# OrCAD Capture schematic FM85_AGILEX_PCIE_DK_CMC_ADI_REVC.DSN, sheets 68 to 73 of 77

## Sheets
68 1p2V_PRE: size B
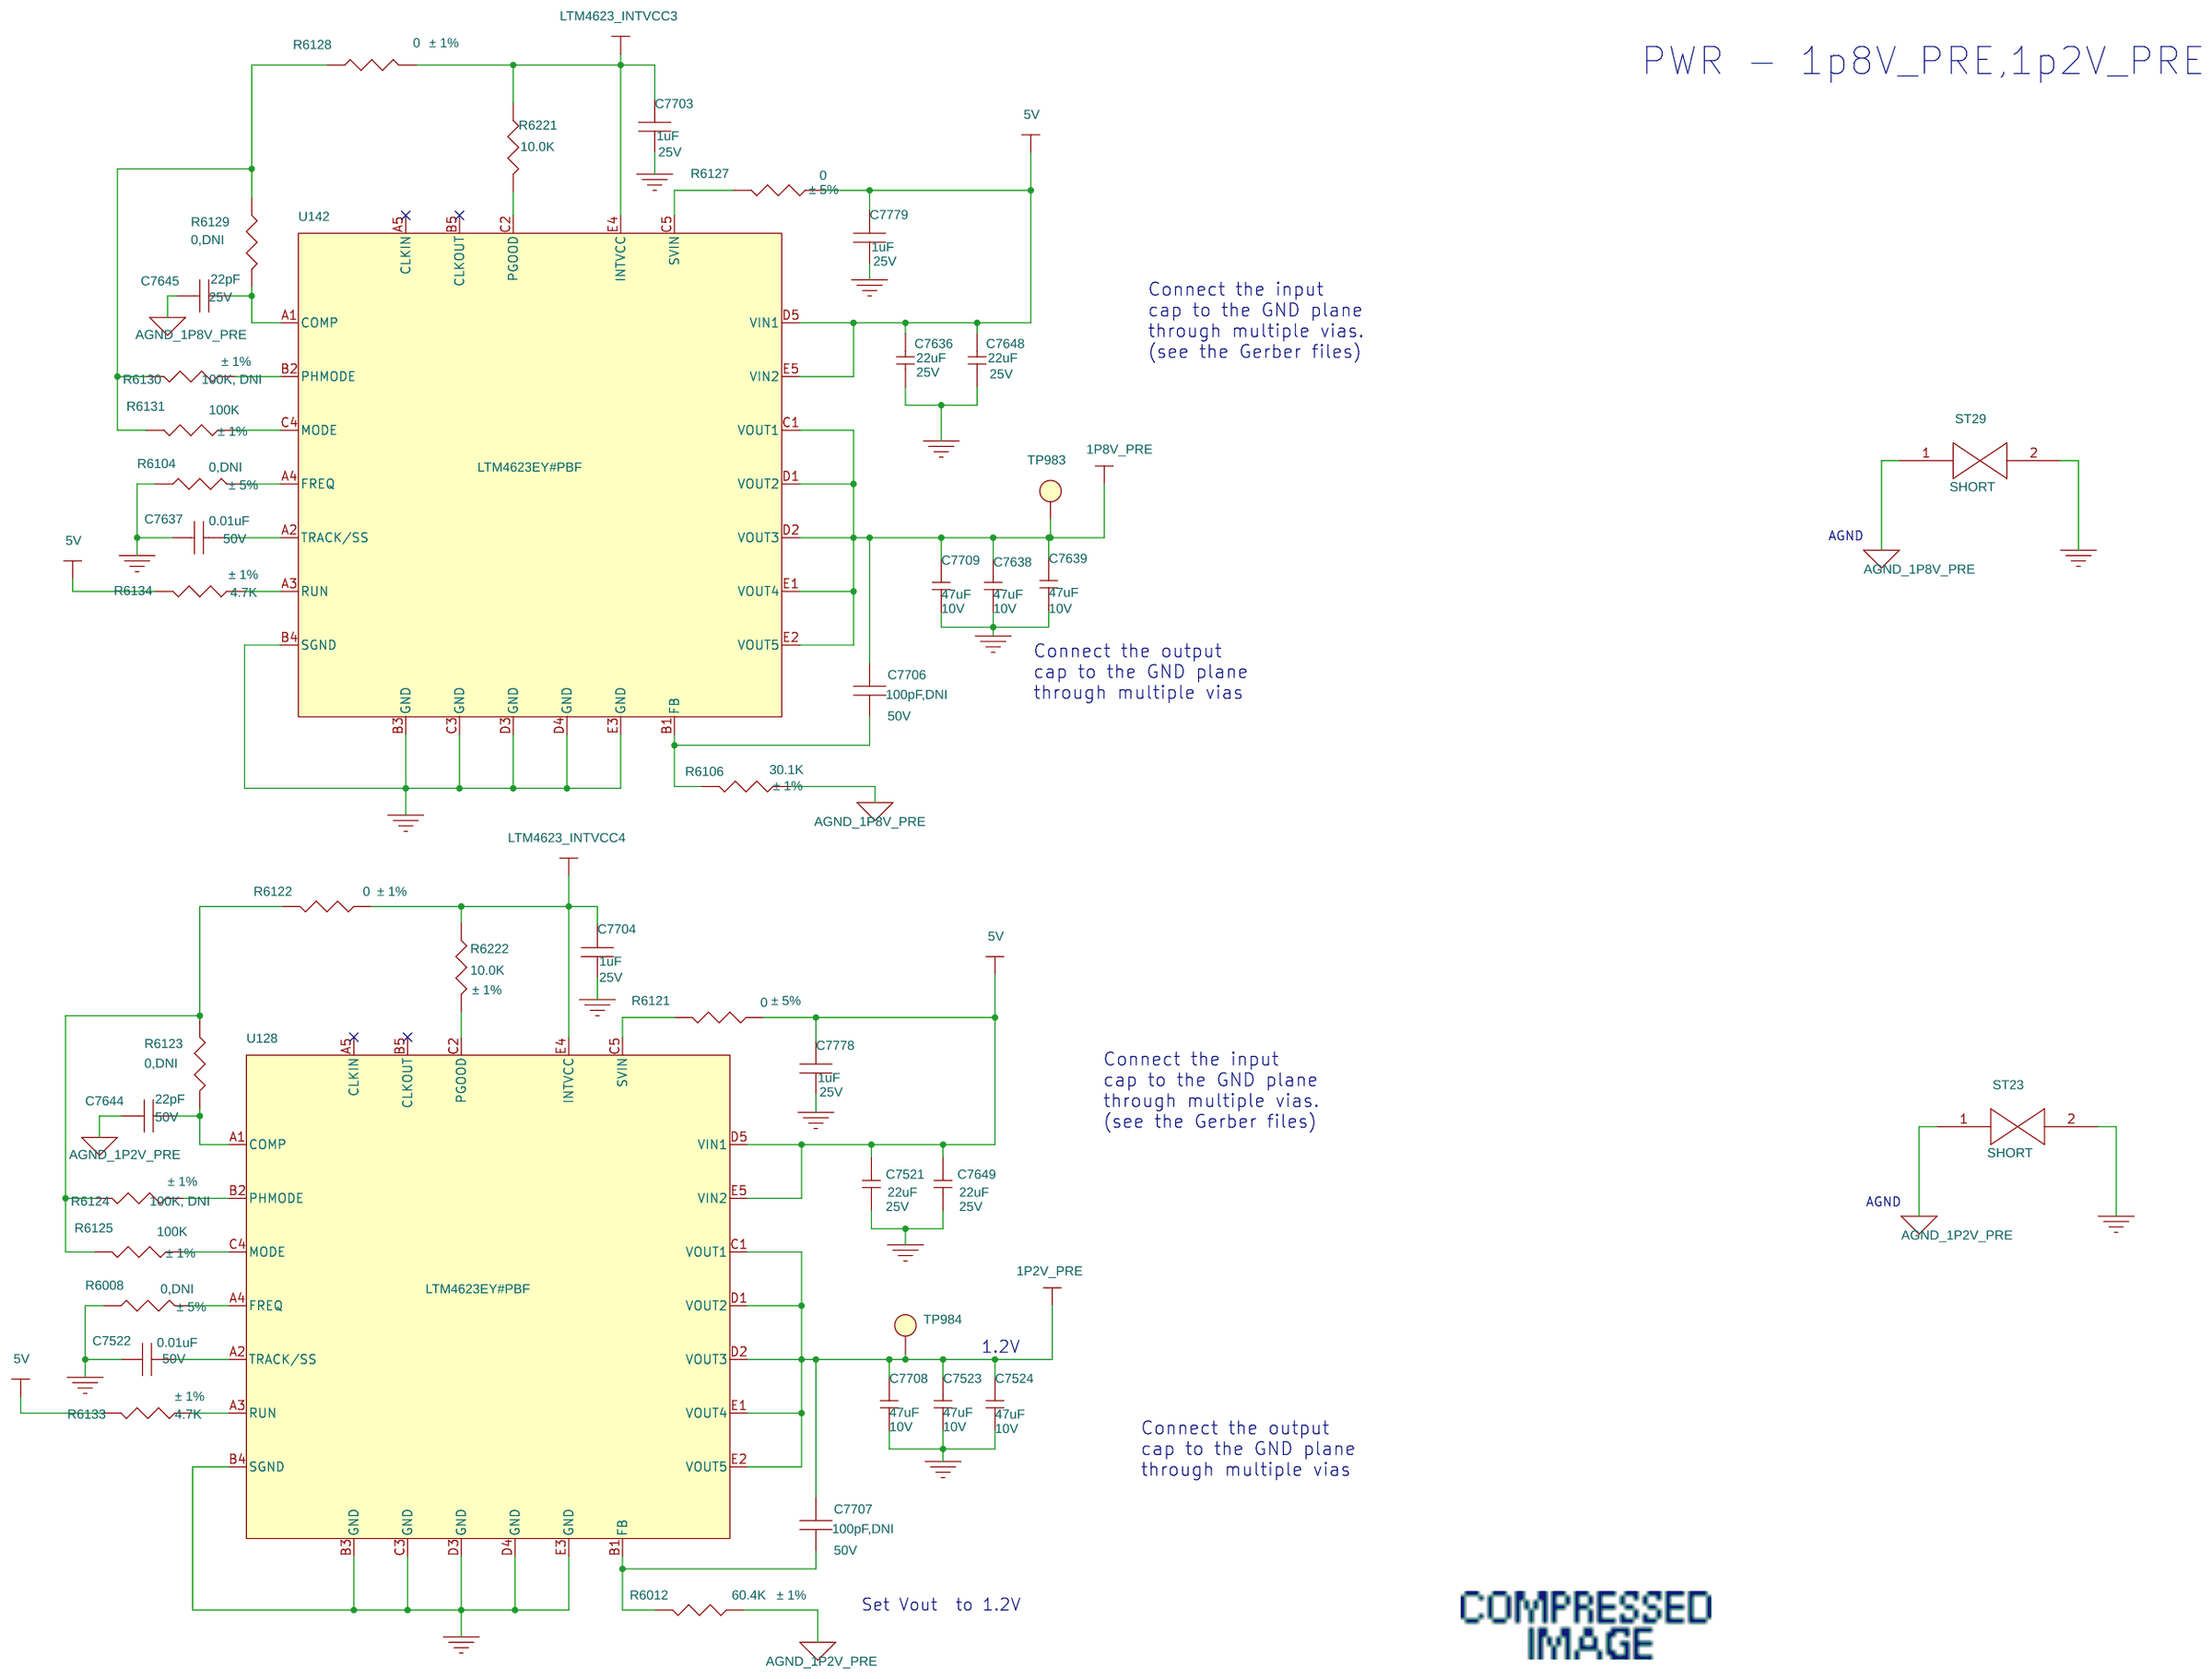
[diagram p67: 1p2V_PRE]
69 PWR-VCCFUSEWR_SDM: size B
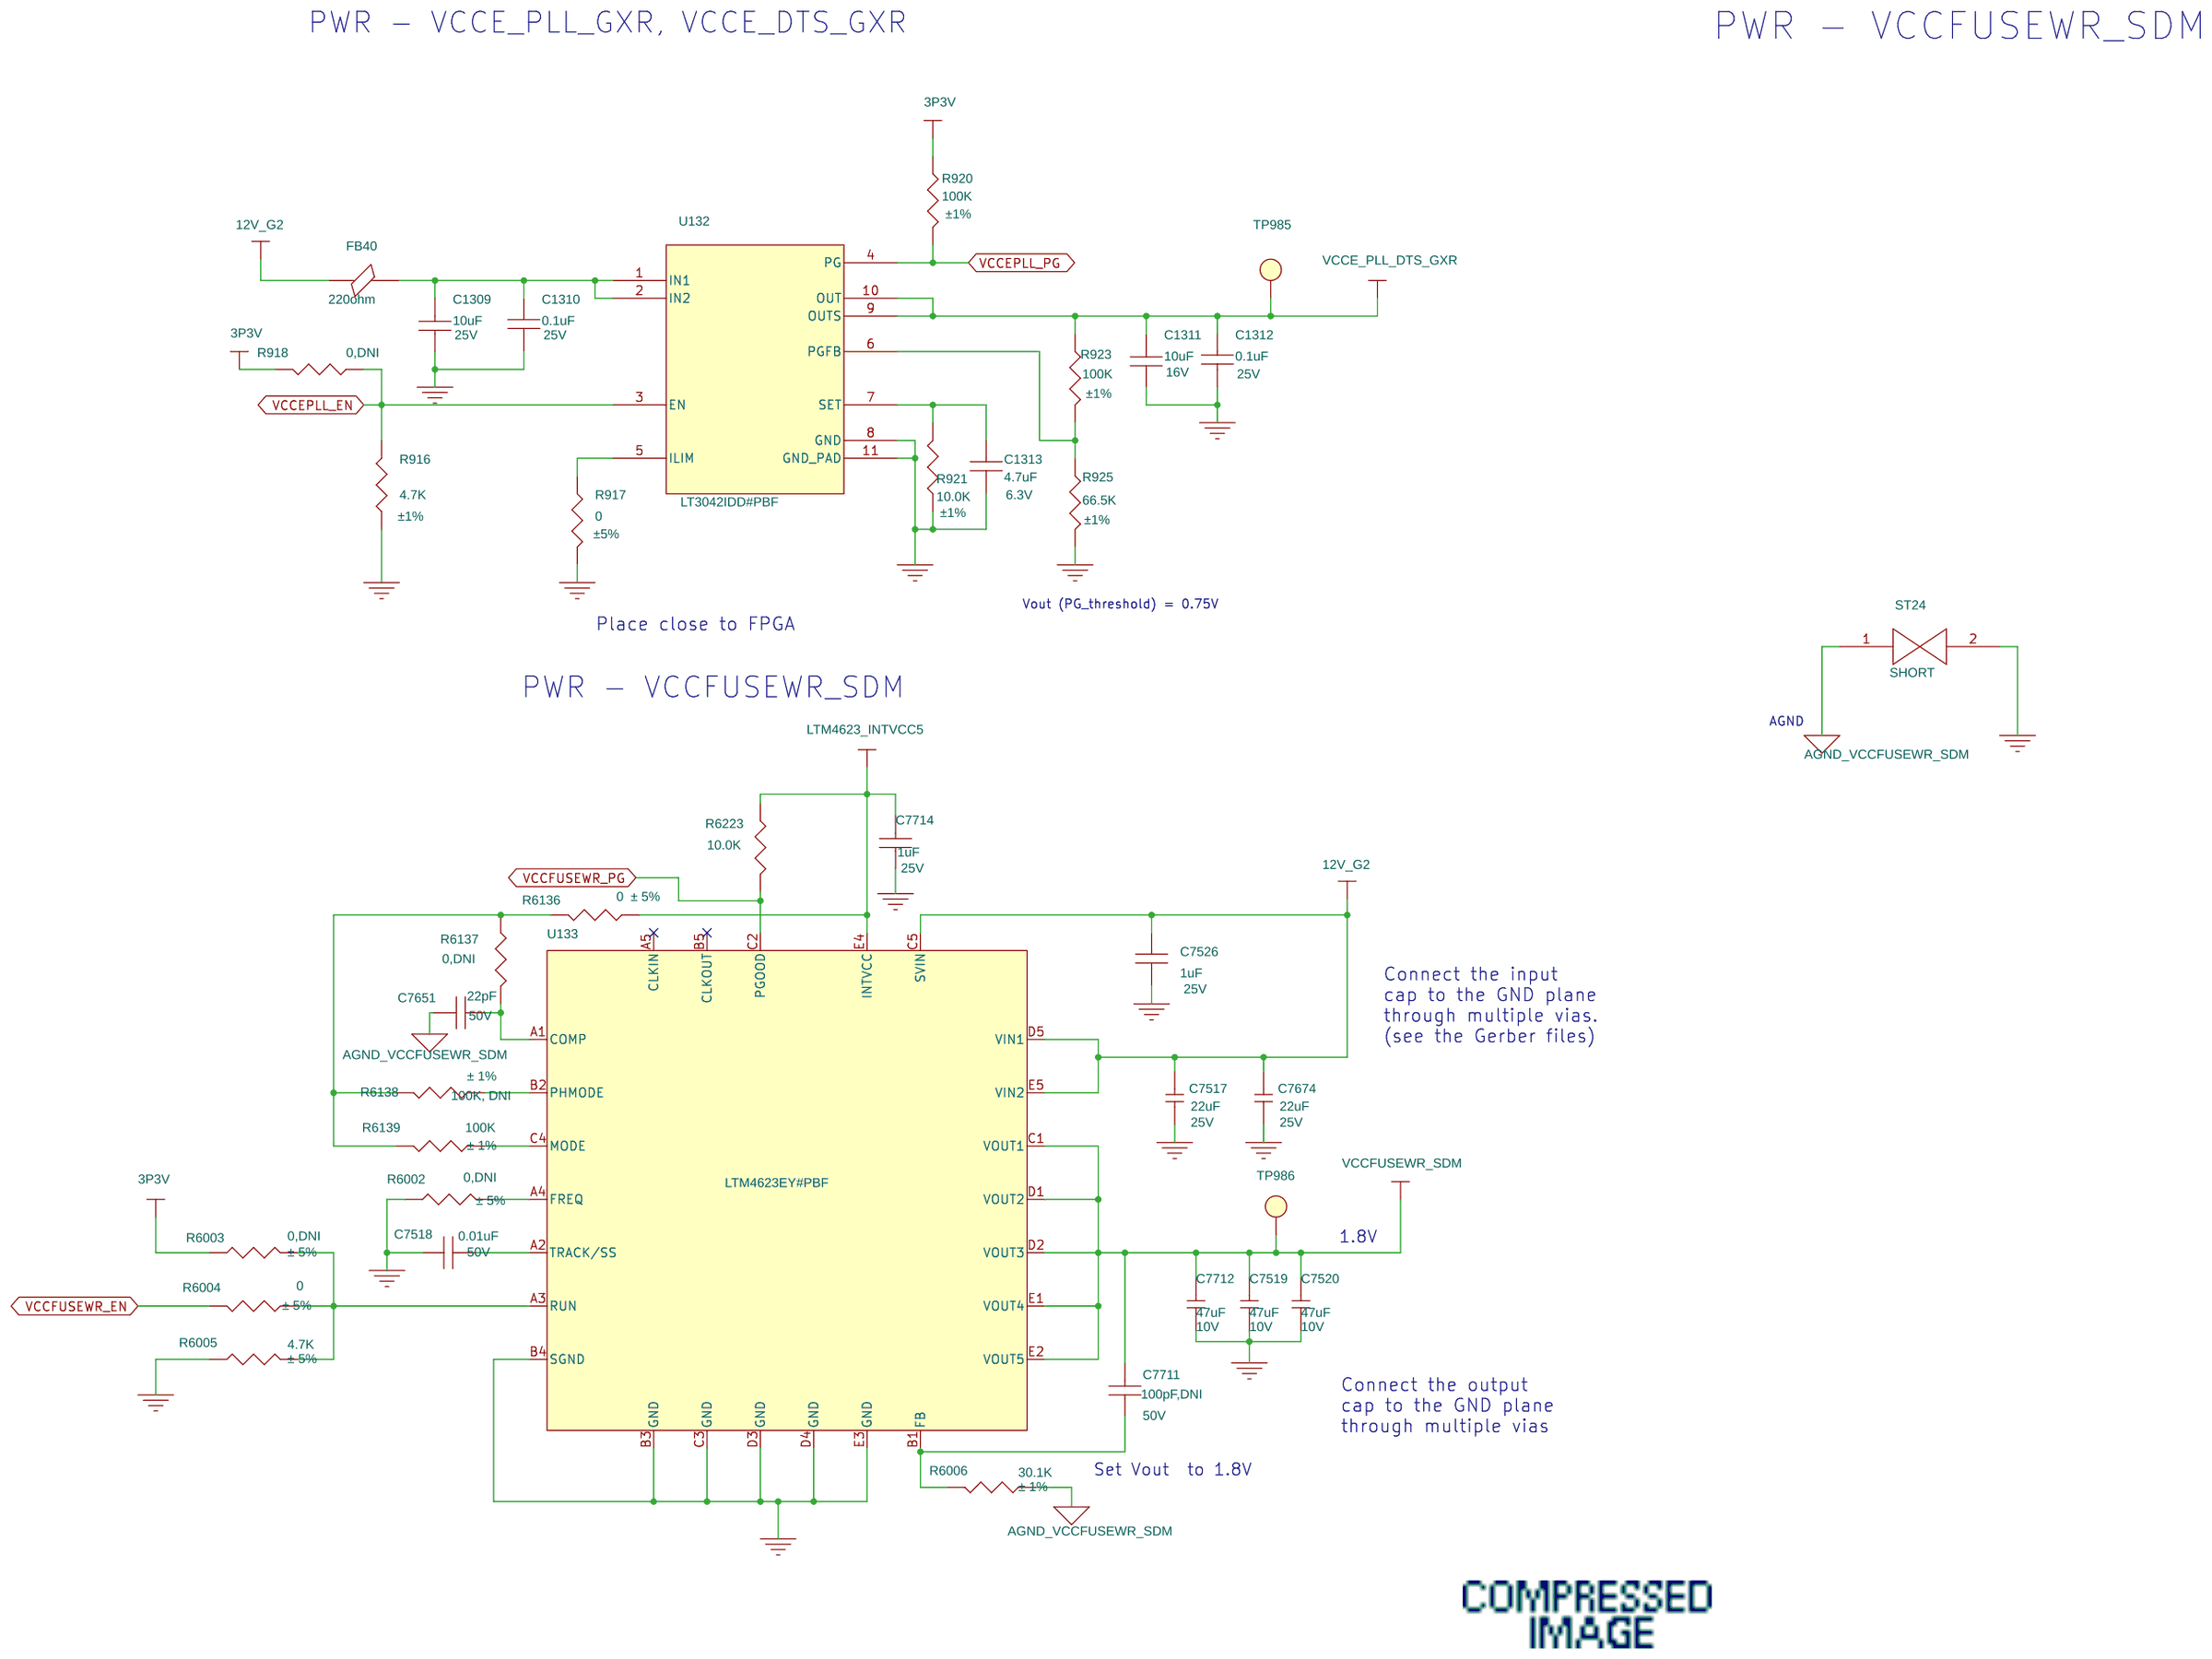
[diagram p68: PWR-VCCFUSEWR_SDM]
70 PWR - 1p2V_DDR4_CH01_OK: size B
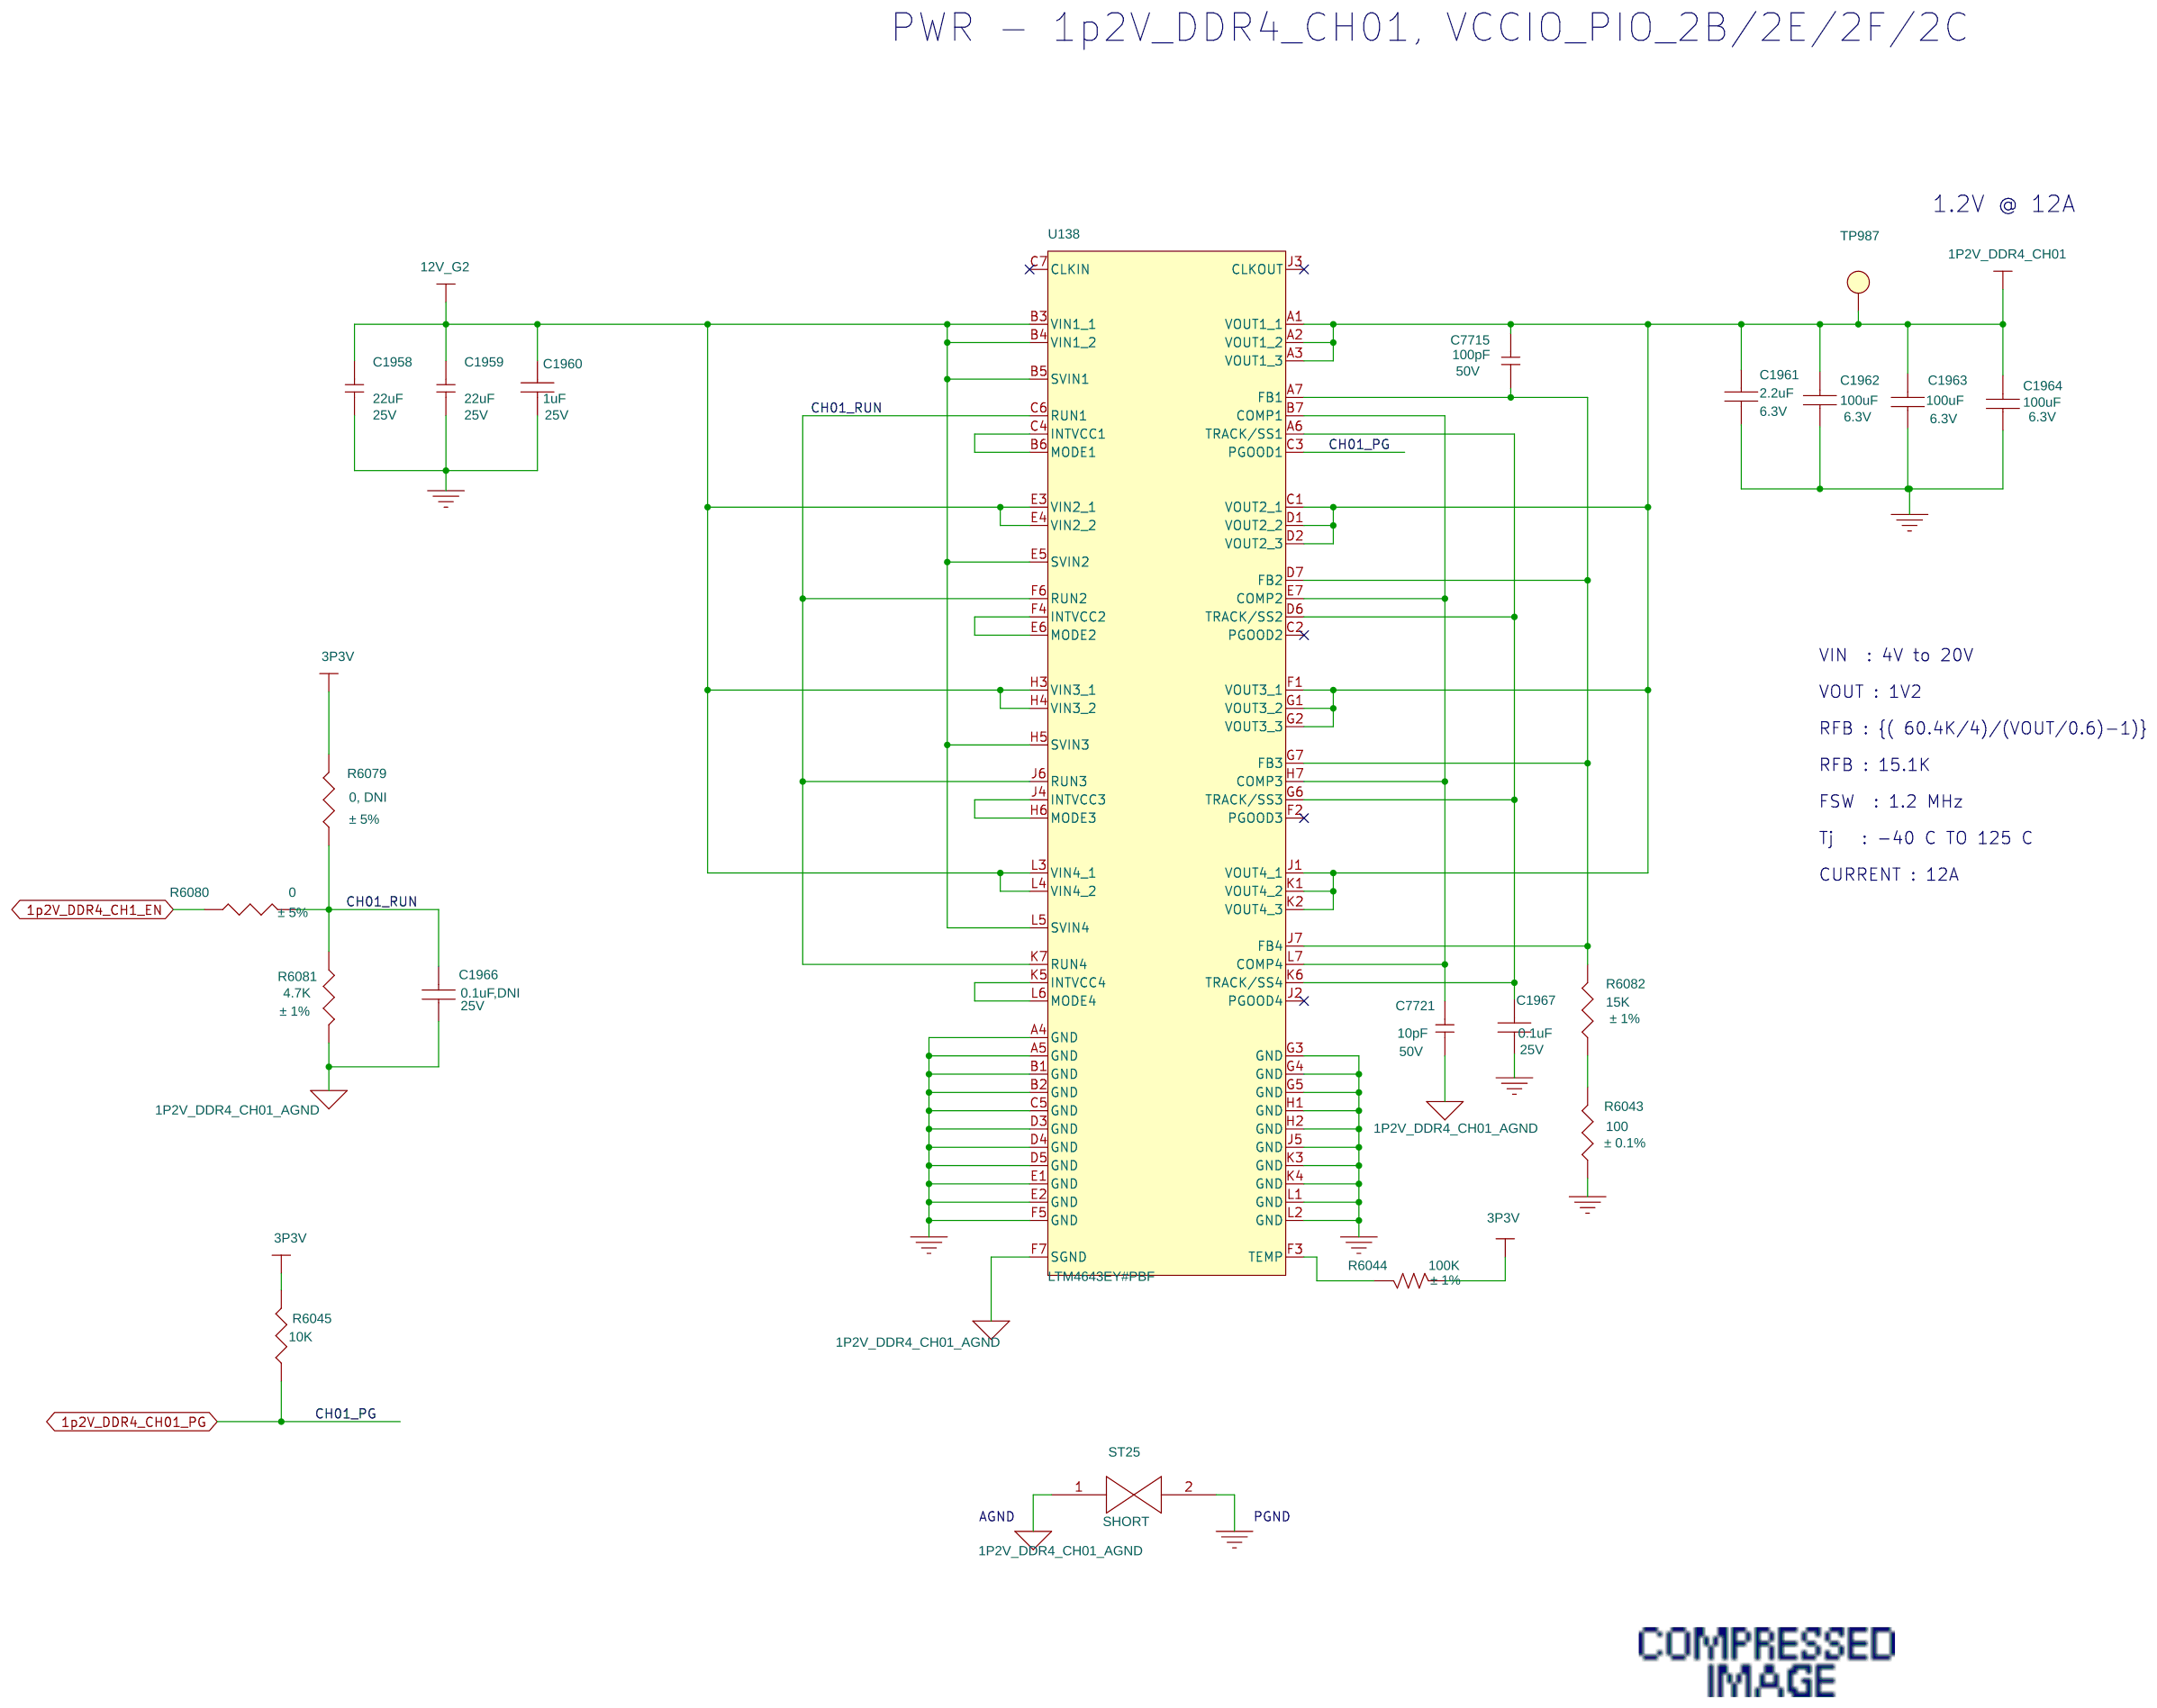
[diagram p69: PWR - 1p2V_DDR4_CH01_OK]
71 PWR - 1p2V_DDR4_CH2_OK: size B
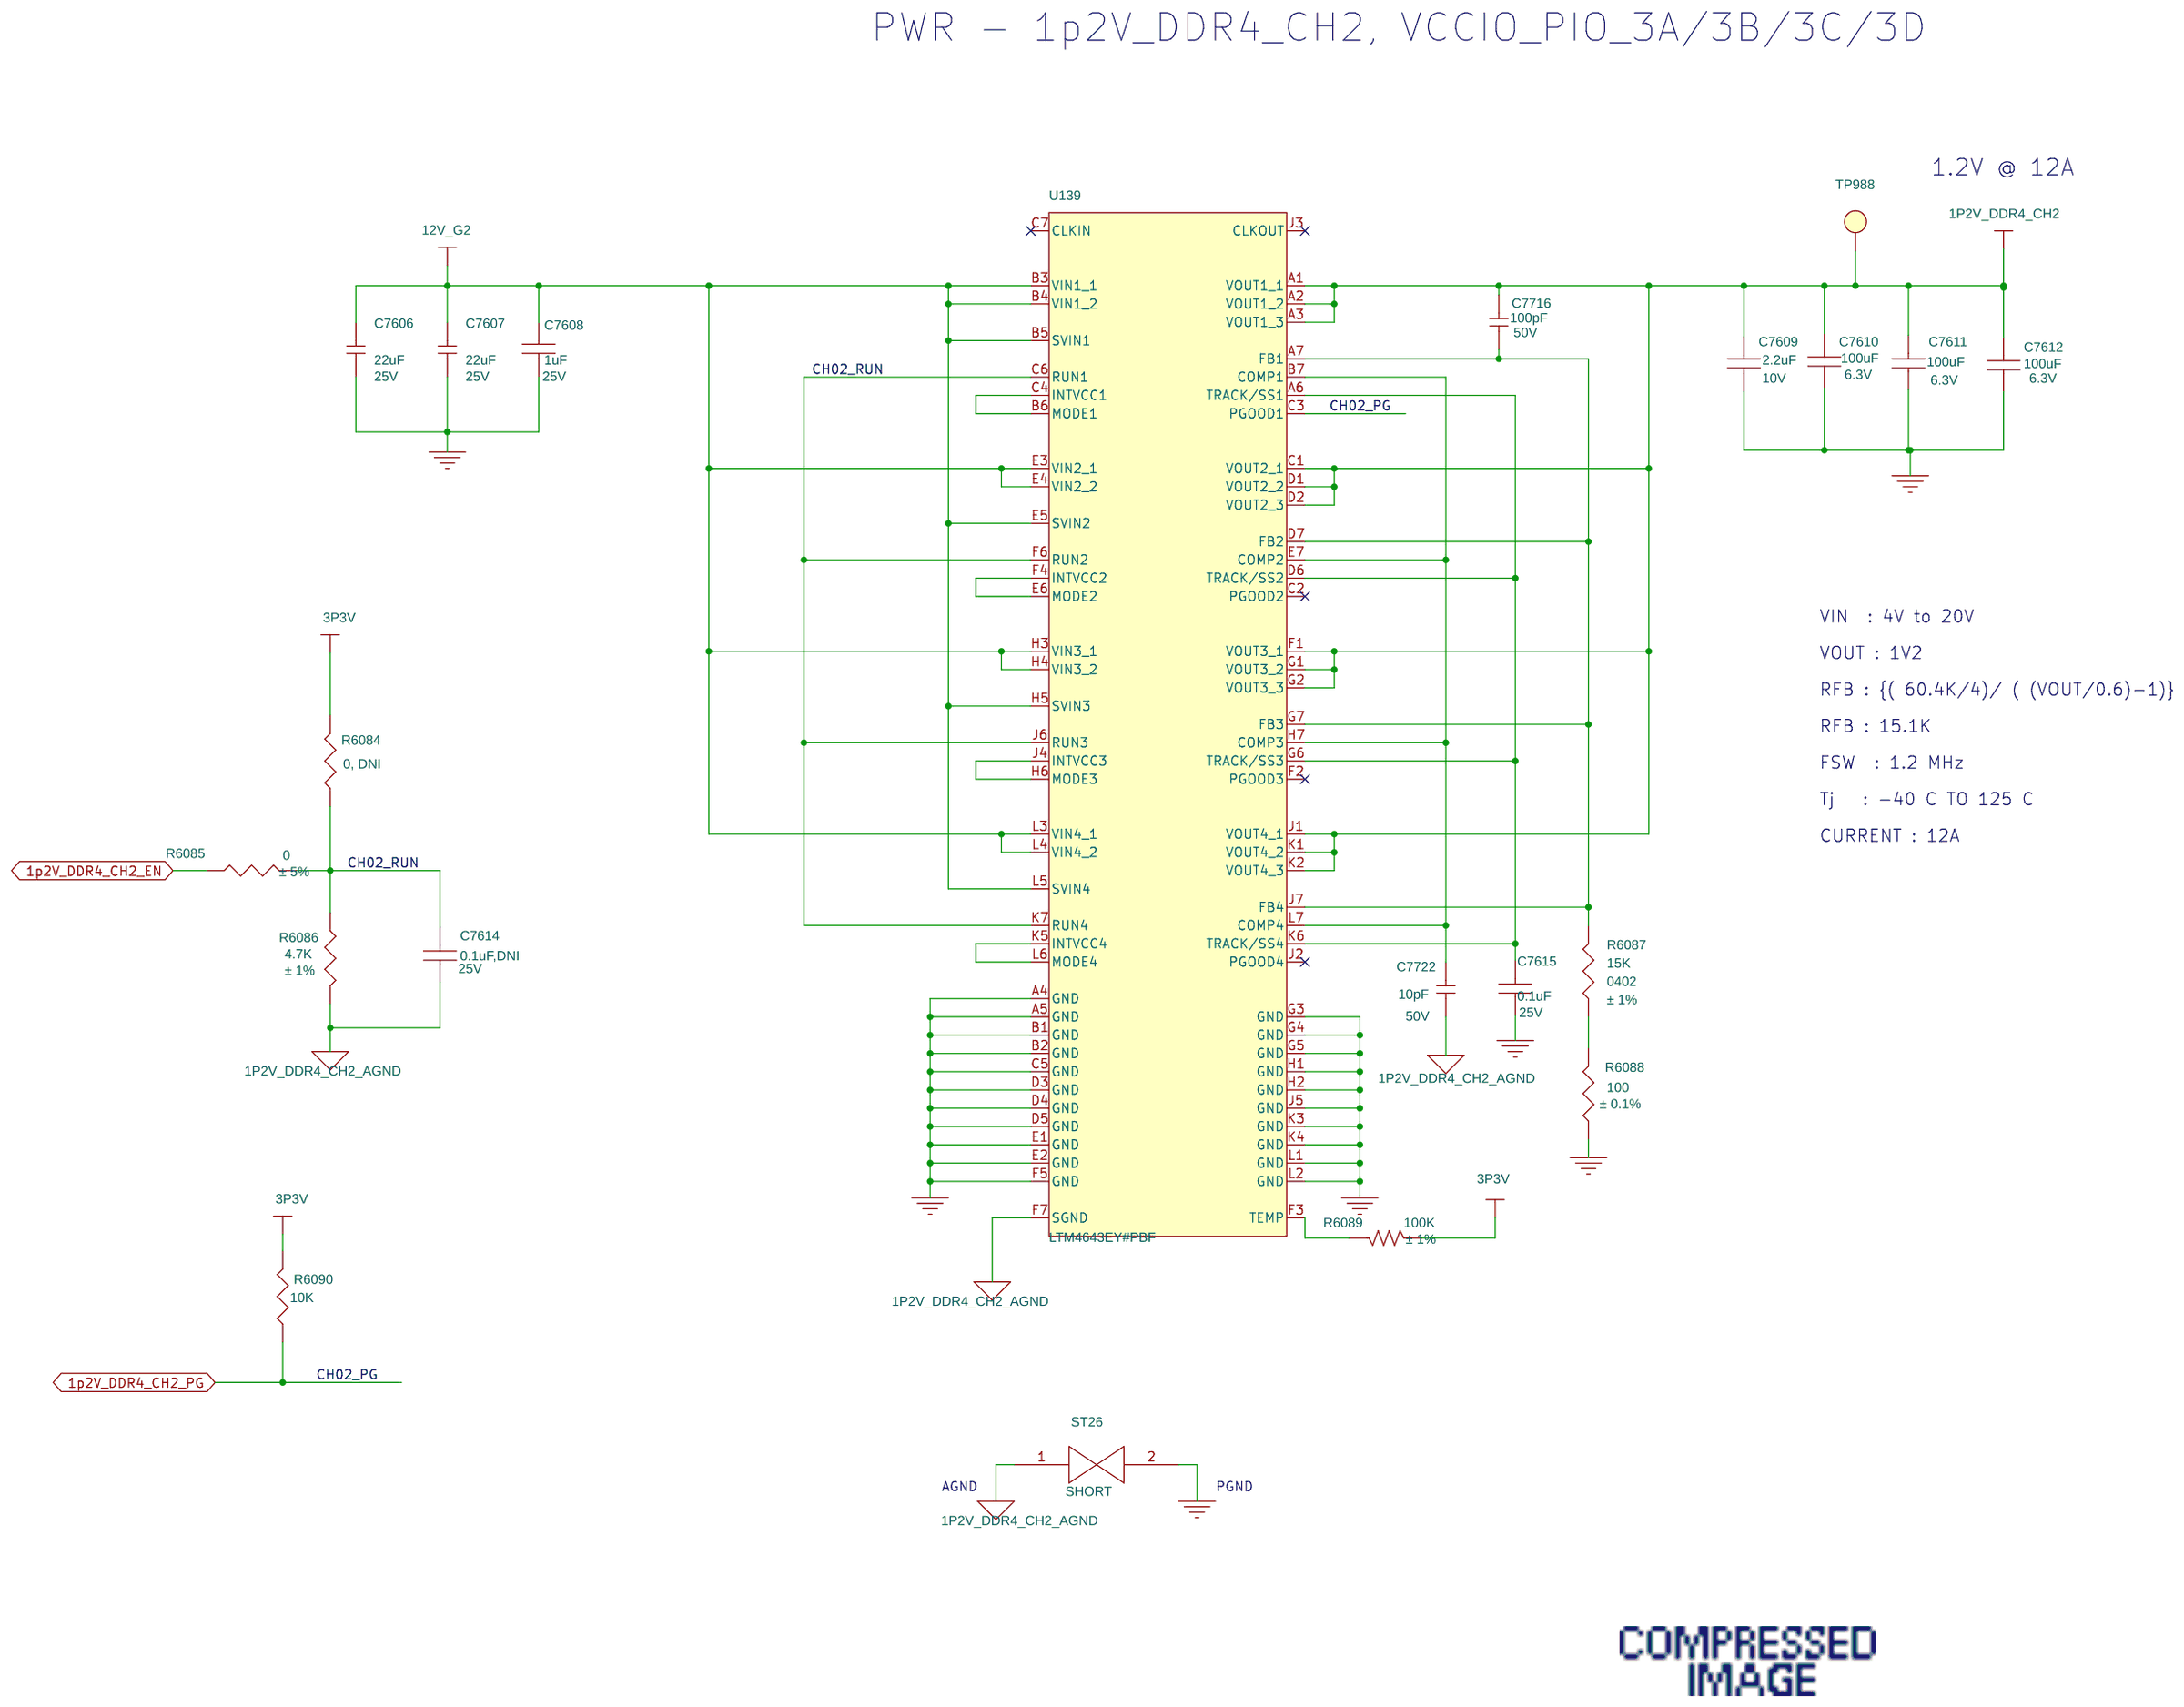
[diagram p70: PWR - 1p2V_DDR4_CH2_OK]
72 PWR - 0p6V_VTT/VREF_OK: size B
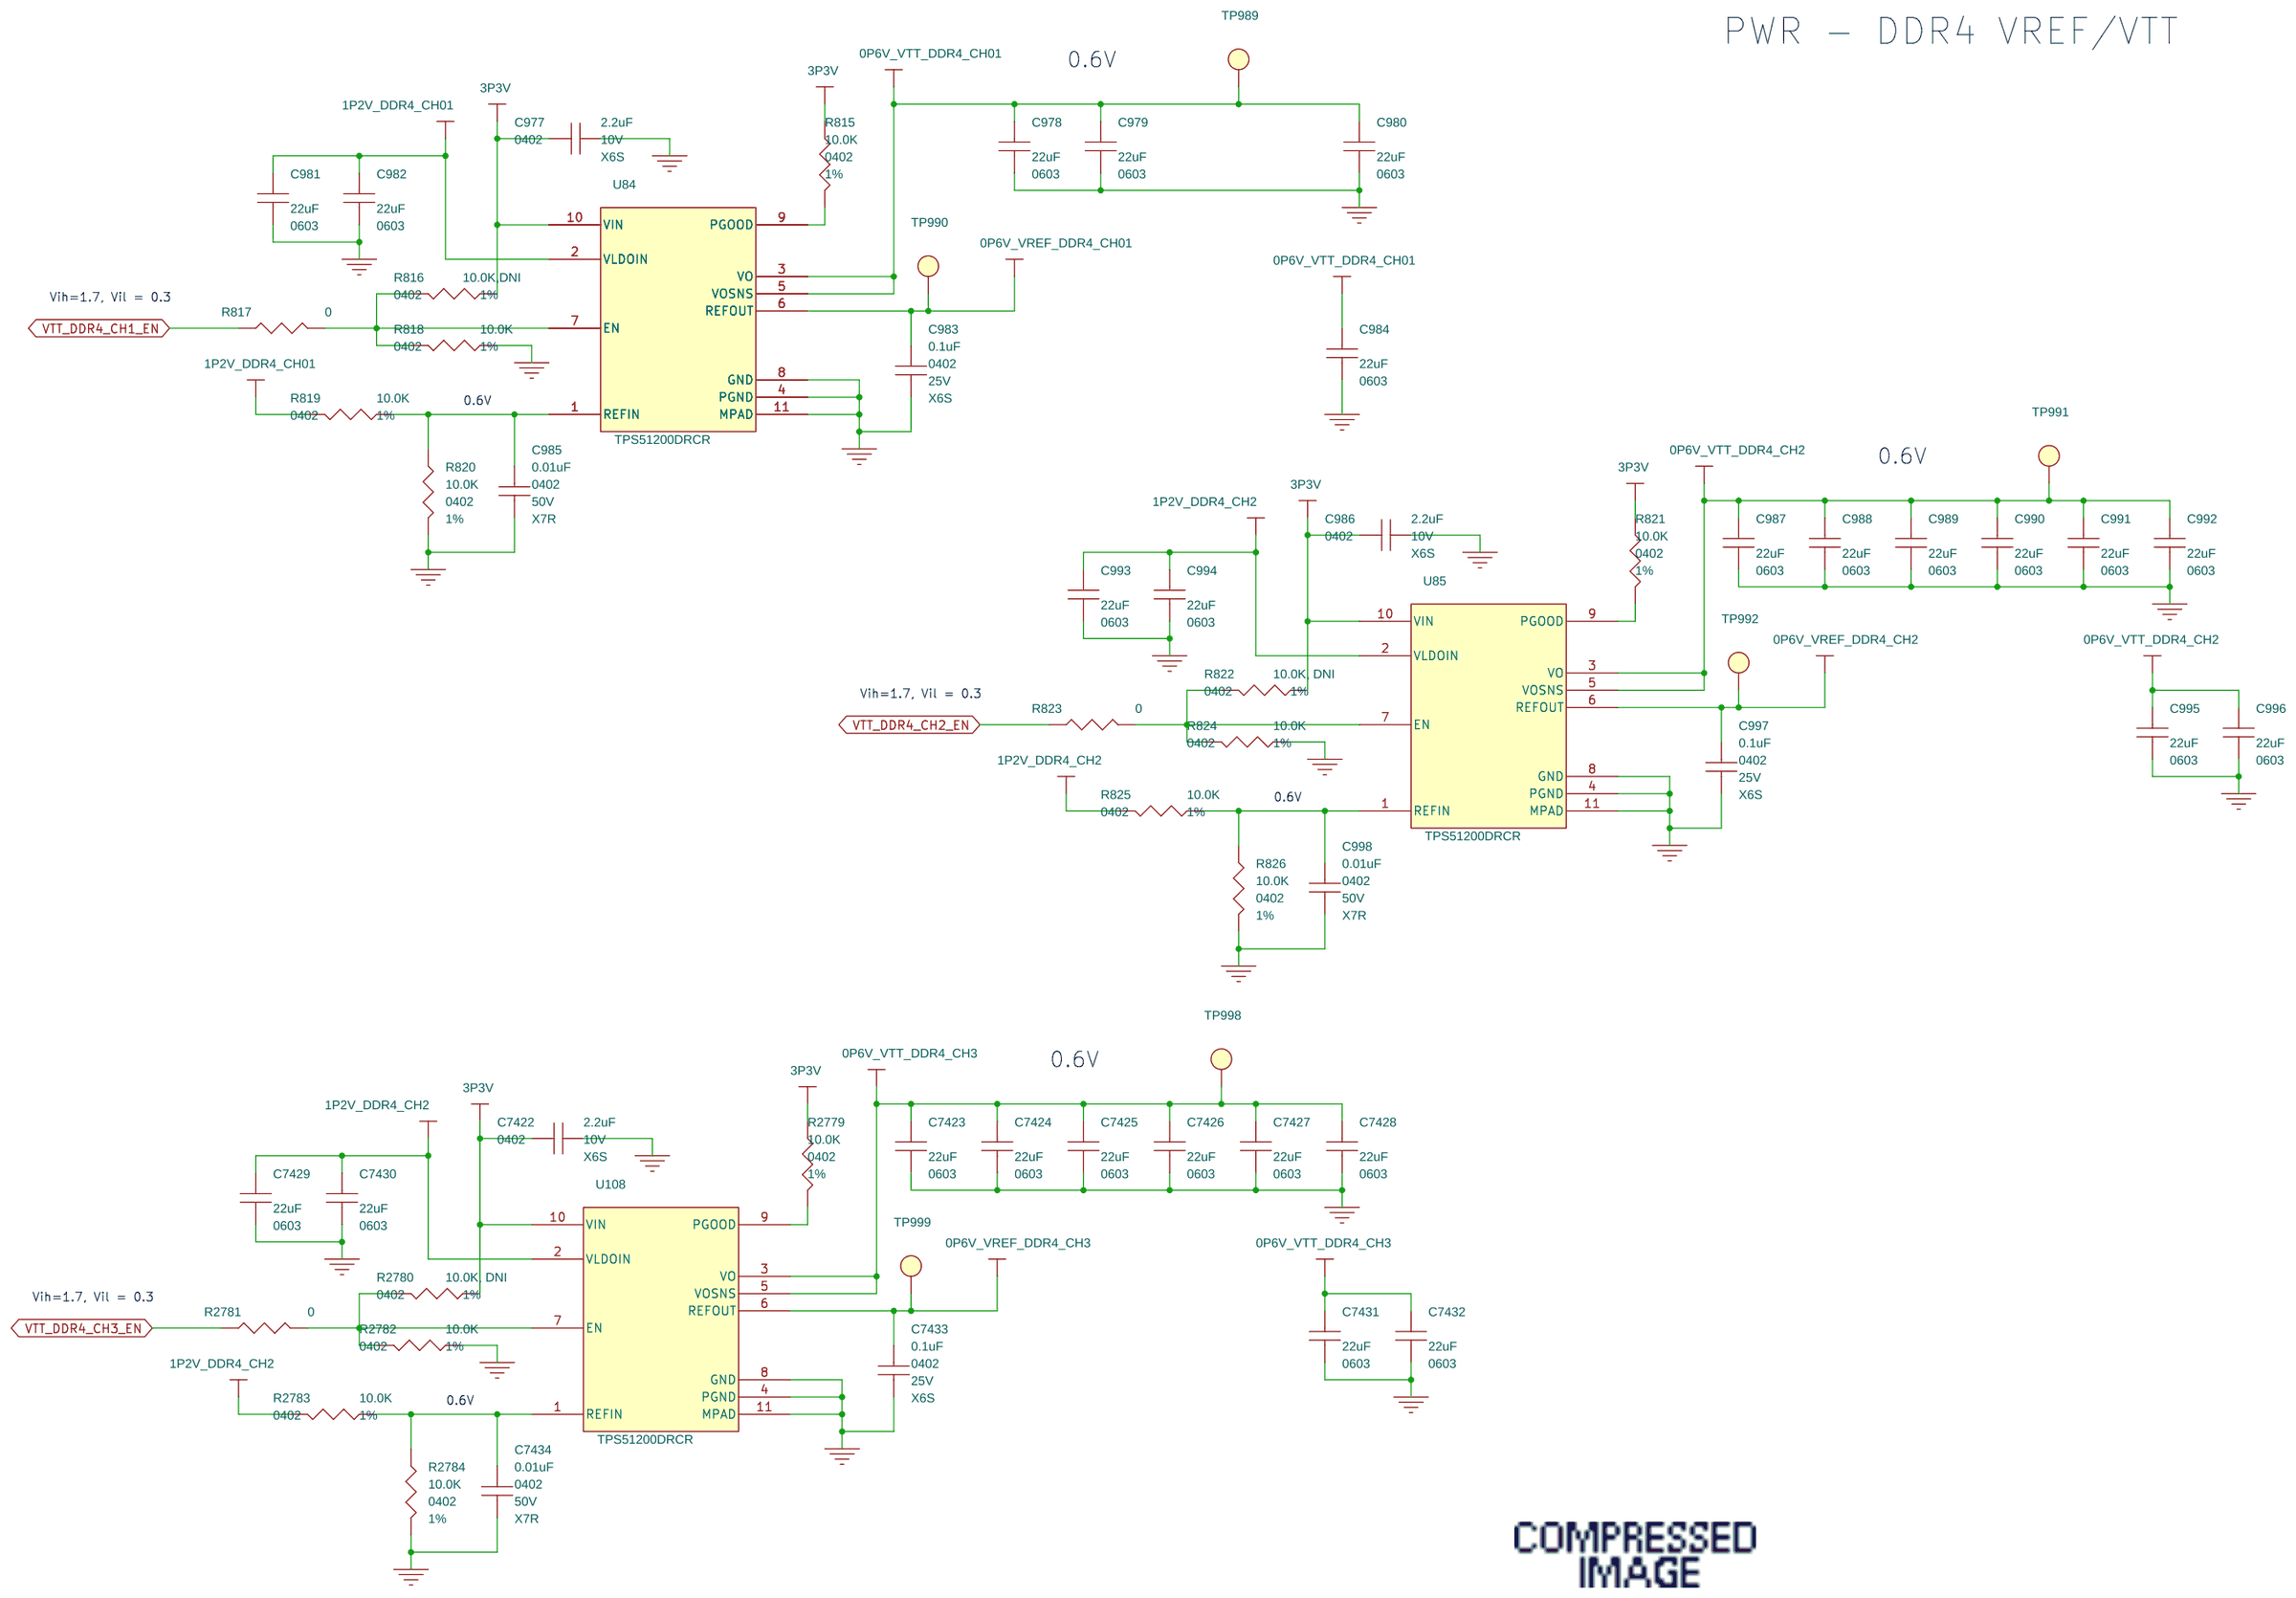
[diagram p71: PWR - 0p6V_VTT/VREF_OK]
73 PWR - 2p5V_OK: size B
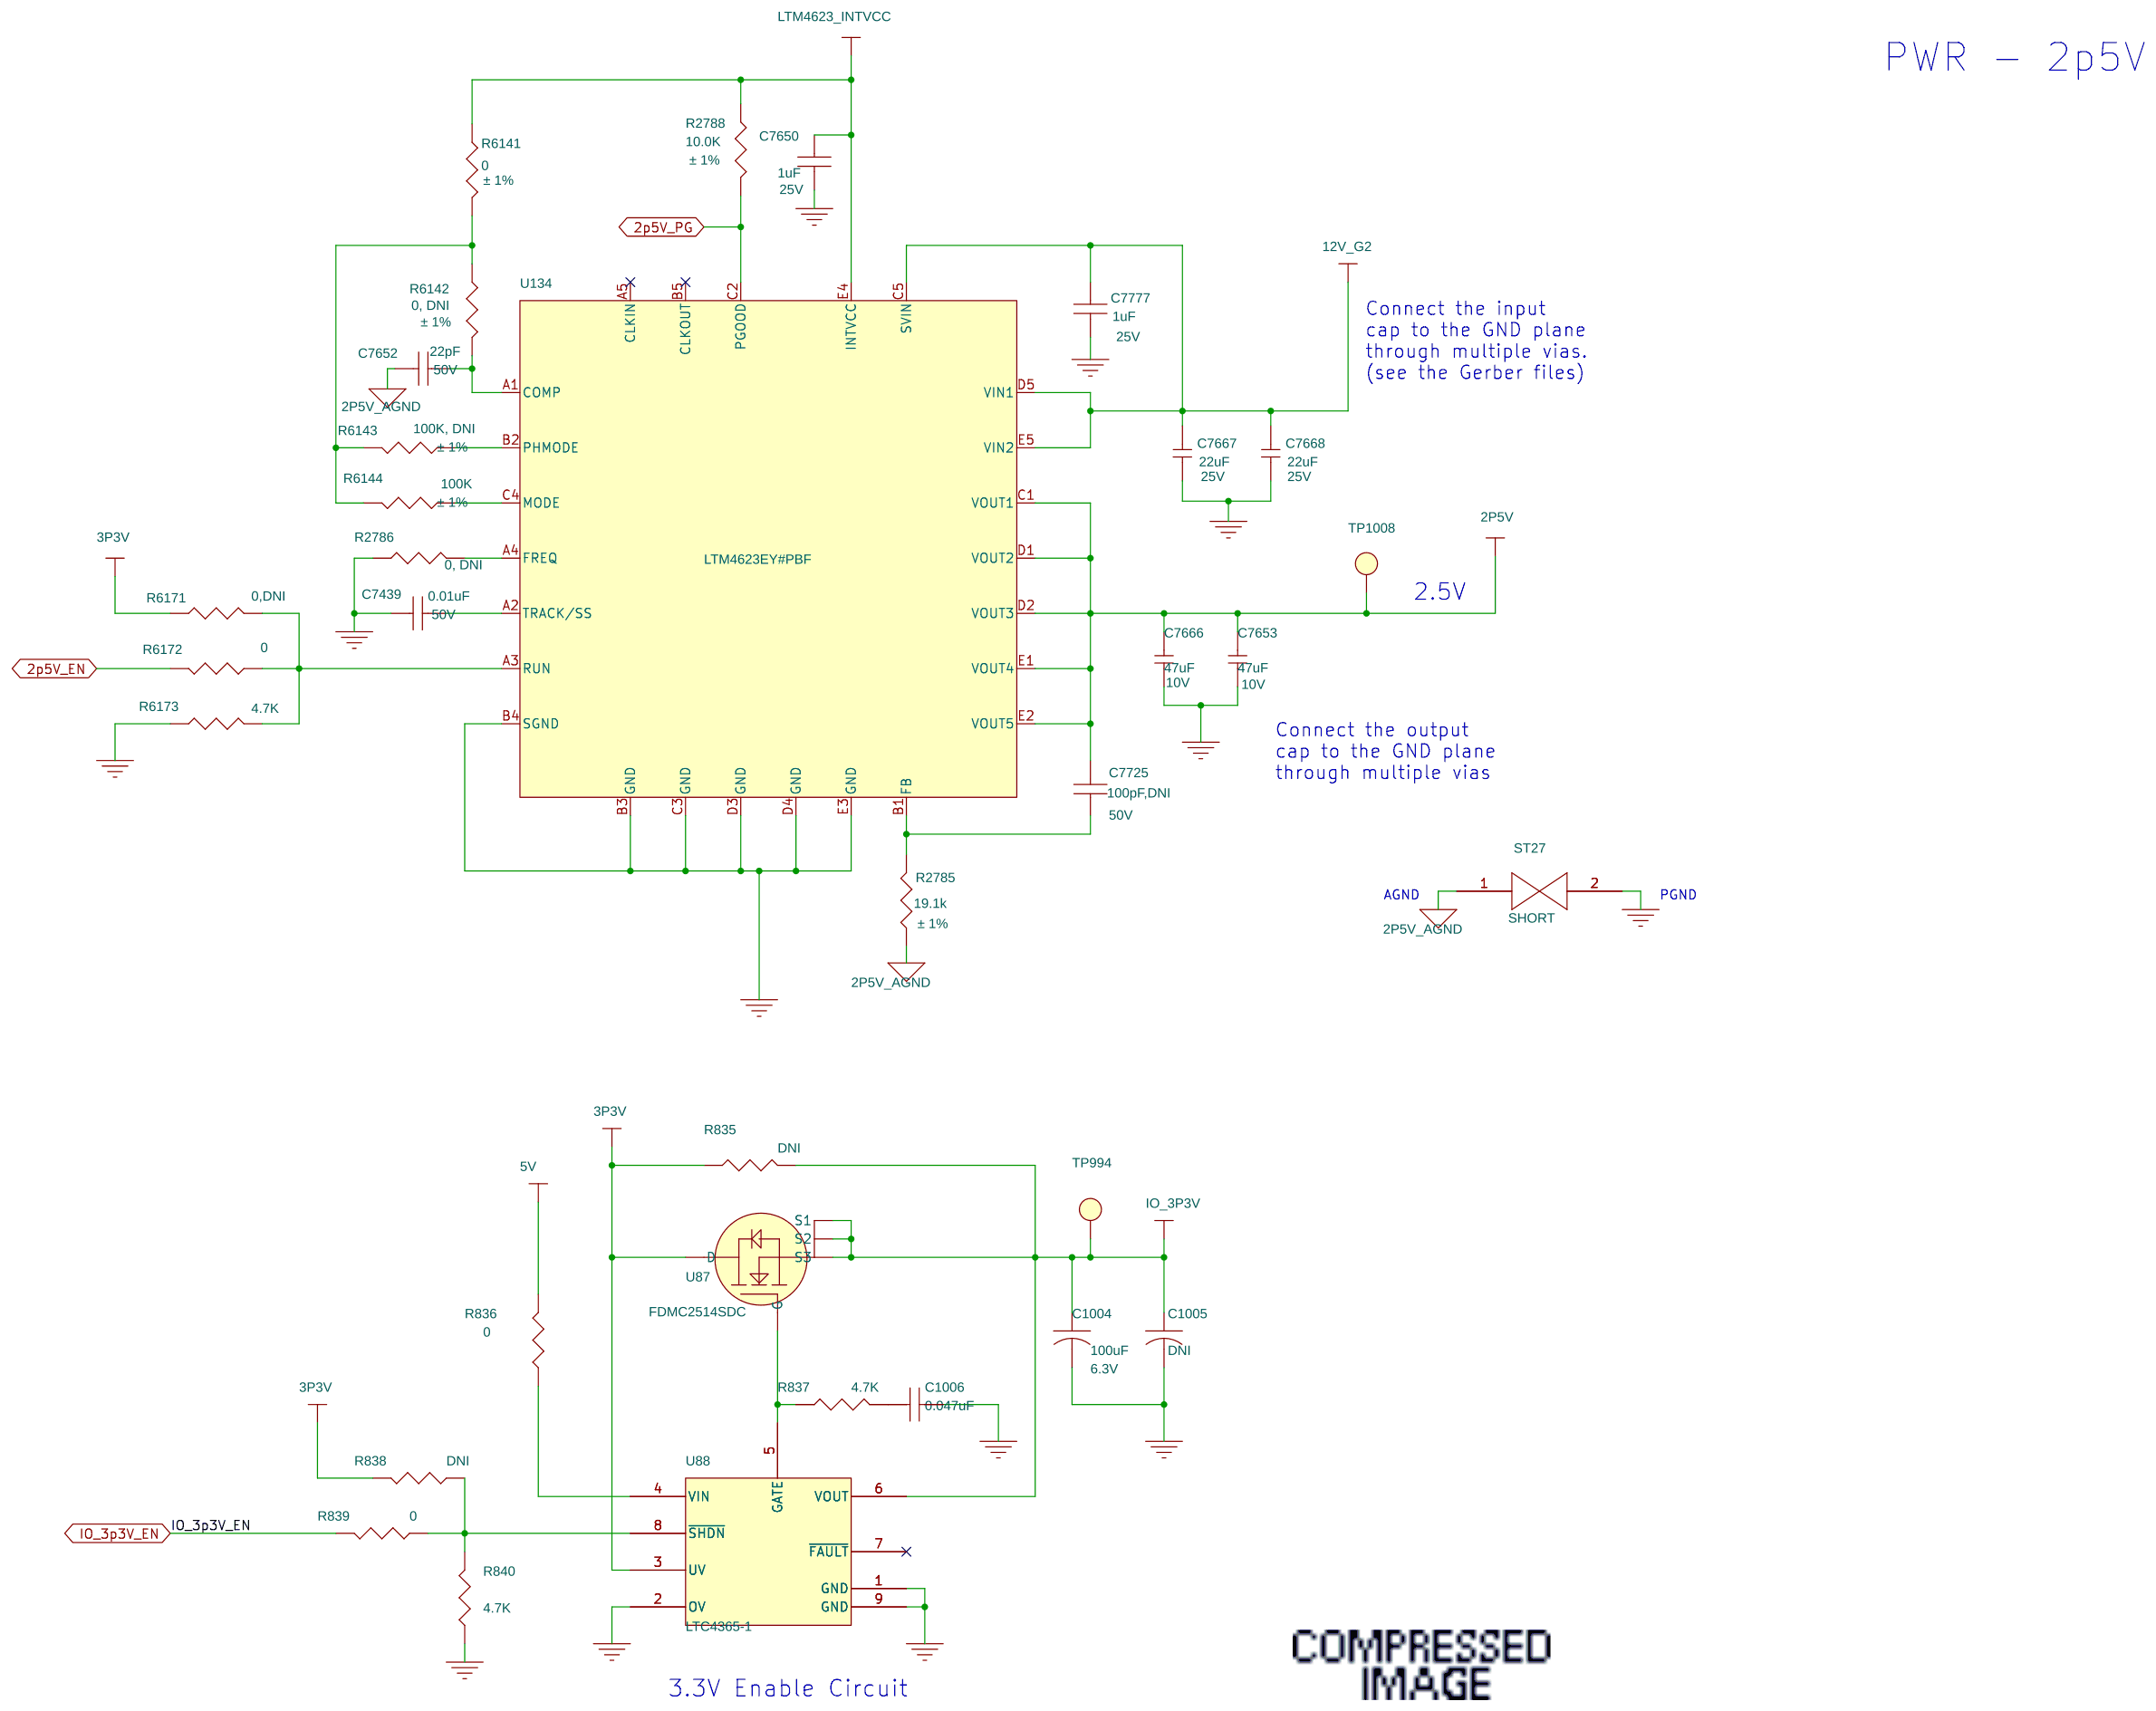
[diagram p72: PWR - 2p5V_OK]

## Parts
sheet 1p2V_PRE
C7521  22uF  [1206]
C7522  0.01uF  [0402]
C7523  47uF  [C1206]
C7524  47uF  [C1206]
C7636  22uF  [1206]
C7637  0.01uF  [0402]
C7638  47uF  [C1206]
C7639  47uF  [C1206]
C7644  22pF  [0603]
C7645  22pF  [0603]
C7648  22uF  [1206]
C7649  22uF  [1206]
C7703  1uF  [0402]
C7704  1uF  [0402]
C7706  100pF,DNI  [0402]
C7707  100pF,DNI  [0402]
C7708  47uF  [C1206]
C7709  47uF  [C1206]
C7778  1uF  [0402]
C7779  1uF  [0402]
R6008  0,DNI  [0402]
R6012  60.4K  [0402]
R6104  0,DNI  [0402]
R6106  30.1K  [0402]
R6121  0  [0402]
R6122  0  [0402]
R6123  0,DNI  [0402]
R6124  100K, DNI  [0402]
R6125  100K  [0402]
R6127  0  [0402]
R6128  0  [0402]
R6129  0,DNI  [0402]
R6130  100K, DNI  [0402]
R6131  100K  [0402]
R6133  4.7K  [0402]
R6134  4.7K  [0402]
R6221  10.0K  [0402]
R6222  10.0K  [0402]
ST23  SHORT  [SHORT]
ST29  SHORT  [SHORT]
TP983  TESTPOINT  [30MIL_TP]
TP984  TESTPOINT  [30MIL_TP]
U128  LTM4623EY#PBF  [BGA25C127P5X5_625X625X262]
U142  LTM4623EY#PBF  [BGA25C127P5X5_625X625X262]
sheet PWR - 0p6V_VTT/VREF_OK
C977  2.2uF  [0402]
C978  22uF  [0603]
C979  22uF  [0603]
C980  22uF  [0603]
C981  22uF  [0603]
C982  22uF  [0603]
C983  0.1uF  [0402]
C984  22uF  [0603]
C985  0.01uF  [0402]
C986  2.2uF  [0402]
C987  22uF  [0603]
C988  22uF  [0603]
C989  22uF  [0603]
C990  22uF  [0603]
C991  22uF  [0603]
C992  22uF  [0603]
C993  22uF  [0603]
C994  22uF  [0603]
C995  22uF  [0603]
C996  22uF  [0603]
C997  0.1uF  [0402]
C998  0.01uF  [0402]
C7422  2.2uF  [0402]
C7423  22uF  [0603]
C7424  22uF  [0603]
C7425  22uF  [0603]
C7426  22uF  [0603]
C7427  22uF  [0603]
C7428  22uF  [0603]
C7429  22uF  [0603]
C7430  22uF  [0603]
C7431  22uF  [0603]
C7432  22uF  [0603]
C7433  0.1uF  [0402]
C7434  0.01uF  [0402]
R815  10.0K  [0402]
R816  10.0K,DNI  [0402]
R817  0  [0402]
R818  10.0K  [0402]
R819  10.0K  [0402]
R820  10.0K  [0402]
R821  10.0K  [0402]
R822  10.0K, DNI  [0402]
R823  0  [0402]
R824  10.0K  [0402]
R825  10.0K  [0402]
R826  10.0K  [0402]
R2779  10.0K  [0402]
R2780  10.0K, DNI  [0402]
R2781  0  [0402]
R2782  10.0K  [0402]
R2783  10.0K  [0402]
R2784  10.0K  [0402]
TP989  TESTPOINT  [30MIL_TP]
TP990  TESTPOINT  [30MIL_TP]
TP991  TESTPOINT  [30MIL_TP]
TP992  TESTPOINT  [30MIL_TP]
TP998  TESTPOINT  [30MIL_TP]
TP999  TESTPOINT  [30MIL_TP]
U84  TPS51200DRCR  [VSON-11]
U85  TPS51200DRCR  [VSON-11]
U108  TPS51200DRCR  [VSON-11]
sheet PWR - 1p2V_DDR4_CH01_OK
C1958  22uF  [1206]
C1959  22uF  [1206]
C1960  1uF  [0402]
C1961  2.2uF  [0603]
C1962  100uF  [1206]
C1963  100uF  [1206]
C1964  100uF  [1206]
C1966  0.1uF,DNI  [0402]
C1967  0.1uF  [0402]
C7715  100pF  [0402]
C7721  10pF  [0402]
R6043  100  [RESC1005X40L20L]
R6044  100K  [R0402]
R6045  10K  [0402]
R6079  0, DNI  [0402]
R6080  0  [0402]
R6081  4.7K  [0402]
R6082  15K  [0402]
ST25  SHORT  [SHORT]
TP987  TESTPOINT  [30MIL_TP]
U138  LTM4643EY#PBF  [BGA77C127P7X11_900X1500X262N]
sheet PWR - 1p2V_DDR4_CH2_OK
C7606  22uF  [1206]
C7607  22uF  [1206]
C7608  1uF  [0402]
C7609  2.2uF  [0603]
C7610  100uF  [1206]
C7611  100uF  [1206]
C7612  100uF  [1206]
C7614  0.1uF,DNI  [0402]
C7615  0.1uF  [0402]
C7716  100pF  [0402]
C7722  10pF  [0402]
R6084  0, DNI  [0402]
R6085  0  [0402]
R6086  4.7K  [0402]
R6087  15K  [0402]
R6088  100  [RESC1005X40L20L]
R6089  100K  [R0402]
R6090  10K  [0402]
ST26  SHORT  [SHORT]
TP988  TESTPOINT  [30MIL_TP]
U139  LTM4643EY#PBF  [BGA77C127P7X11_900X1500X262N]
sheet PWR - 2p5V_OK
C1004  100uF  [B2]
C1005  DNI  [1210]
C1006  0.047uF  [0402]
C7439  0.01uF  [0402]
C7650  1uF  [0402]
C7652  22pF  [0603]
C7653  47uF  [C1206]
C7666  47uF  [C1206]
C7667  22uF  [1206]
C7668  22uF  [1206]
C7725  100pF,DNI  [0402]
C7777  1uF  [0402]
R835  DNI  [1206]
R836  0  [0402]
R837  4.7K  [0402]
R838  DNI  [0402]
R839  0  [0402]
R840  4.7K  [0402]
R2785  19.1k  [0402]
R2786  0, DNI  [0402]
R2788  10.0K  [0402]
R6141  0  [0402]
R6142  0, DNI  [0402]
R6143  100K, DNI  [0402]
R6144  100K  [0402]
R6171  0,DNI  [0402]
R6172  0  [0402]
R6173  4.7K  [0402]
ST27  SHORT  [SHORT]
TP994  TESTPOINT  [30MIL_TP]
TP1008  TESTPOINT  [30MIL_TP]
U87  FDMC2514SDC  [FDMC8878_VER2]
U88  LTC4365-1  [DFN8-EPAD_3X2]
U134  LTM4623EY#PBF  [BGA25C127P5X5_625X625X262]
sheet PWR-VCCFUSEWR_SDM
C1309  10uF  [C0805]
C1310  0.1uF  [0402]
C1311  10uF  [C0805]
C1312  0.1uF  [0402]
C1313  4.7uF  [0402]
C7517  22uF  [1206]
C7518  0.01uF  [0402]
C7519  47uF  [C1206]
C7520  47uF  [C1206]
C7526  1uF  [0402]
C7651  22pF  [0603]
C7674  22uF  [1206]
C7711  100pF,DNI  [0402]
C7712  47uF  [C1206]
C7714  1uF  [0402]
FB40  220ohm  [0402]
R916  4.7K  [0402]
R917  0  [0402]
R918  0,DNI  [0402]
R920  100K  [0402]
R921  10.0K  [0402]
R923  100K  [0402]
R925  66.5K  [0402]
R6002  0,DNI  [0402]
R6003  0,DNI  [0402]
R6004  0  [0402]
R6005  4.7K  [0402]
R6006  30.1K  [0402]
R6136  0  [0402]
R6137  0,DNI  [0402]
R6138  100K, DNI  [0402]
R6139  100K  [0402]
R6223  10.0K  [0402]
ST24  SHORT  [SHORT]
TP985  TESTPOINT  [30MIL_TP]
TP986  TESTPOINT  [30MIL_TP]
U132  LT3042IDD#PBF  [LT3042IDD]
U133  LTM4623EY#PBF  [BGA25C127P5X5_625X625X262]

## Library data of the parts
C1958 C1959 C7517 C7521 C7606 C7607 C7636 C7648 C7649 C7667 C7668 C7674 = Cap,_NP,_1206: CAP - CER, 22UF, 25V, 10%, X5R, 1206; Item Num: K28232-001; Manufacturer: Murata; Manufacturer Part Num: GRM31CR61E226KE15L; RATED_VOLTAGE: 25V
C7522 C7637 = CAP: CAP - CER, 10NF, 50V, +/-10%, X7R, 0402 SMD; CAPACITANCE: 0.1uF; Item Num: A36096-100; LIFECYCLE_PHASE: Active; Lead Free Status: Lead Free; MFR_LIFECYCLE: Active; Manufacturer: Murata; Manufacturer Part Num: GRM155R71H103KA88D; Num Pins: 2; PART_SUBCLASS: CAPACITORS; Part Class: CAPACITORS; RATED_VOLTAGE: 50V; RoHS Compliant: RoHS Compliant; Tolerance: +/-50V
C7519 C7520 C7523 C7524 C7638 C7639 C7653 C7666 C7708 C7709 C7712 = Cap,_NP,_1206: CAP - CER 47UF 10V 20% X5R 1206; Item Num: K13655-001; Manufacturer: TDK Electronics; Manufacturer Part Num: C3216X5R1A476M160AB; RATED_VOLTAGE: 10V
C7644 C7651 C7652 = CAP_NP: CAPC,C0G,0603,22.000PF,50.000V,+/- 5%,; Item Num: M23241-001; Manufacturer: Murata; Manufacturer Part Num: GRM1885C1H220JA01J; RATED_VOLTAGE: 50V
C7645 = CAP_NP: CAPC,C0G,0603,22.000PF,50.000V,+/- 5%,; Item Num: M23241-001; Manufacturer: Murata; Manufacturer Part Num: GRM1885C1H220JA01J; RATED_VOLTAGE: 25V
C7703 C7704 C7714 C7778 C7779 = CAP: CAP - CER, 1UF, 25V, 10%, X5R, 0402; Item Num: H29050-001; Lead Free Status: Yes; Manufacturer: TDK Electronics; Manufacturer Part Num: CGB2A1X5R1E105K033BC; Num Pins: 2; Part Class: CAPACITORS; RATED_VOLTAGE: 25V; RoHS Compliant: Yes
C7706 C7707 C7711 C7725 = CAP: CAP, CERAMIC, 100pF, 0402, 5%, 50VDC, NPO; CAPACITANCE: 1000pF; Dielectric: X7R; IPN No: A36095-026; Item Num: A36095-026; LIFECYCLE_PHASE: Active; Lead Free Status: Lead Free; Manufacturer: Murata; Manufacturer Part Num: 04025C101KAT2A; Num Pins: 2; Part Class: CAPACITORS; RATED_VOLTAGE: 50V; RoHS Compliant: RoHS Compliant; Tolerance: 10%
R6002 R6008 = RESISTOR: RES D,0402,0.00 OHM,5.00%,1/16W; Altera Part No.: P02-14020R; Item Num: A93549-001; LIFECYCLE_PHASE: Active; Lead Free Status: No; MFR_LIFECYCLE: Active; Manufacturer: YAGEO CORP.; Manufacturer Part Num: RC0402JR-070RL; Num Pins: 2; PART_SUBCLASS: RESISTORS; POWER: 1/16W; Part Class: RESISTORS; Price: 0; RESISTANCE: 0; RoHS Compliant: RoHS Compliant; Tolerance: ± 5%
R6012 = RESISTOR: RES,60.4K,1/16W,1%,0402,SMD; Item Num: K15653-001; Lead Free Status: No; Manufacturer: Rohm; Manufacturer Part Num: CRCW040260K4FKED; Manufacturer's Part No.: CRCW040260K4FKED; Num Pins: 2; Part Class: RESISTORS; Price: 0; RoHS Compliant: Yes; Tolerance: ± 1%
R6104 = RESISTOR: RES D,0402,0.00 OHM,5.00%,1/16W; Altera Part No.: P02-14020R; Item Num: A93549-001; LIFECYCLE_PHASE: Active; Lead Free Status: No; MFR_LIFECYCLE: Active; Manufacturer: YAGEO CORP.; Manufacturer Part Num: ERJ-2GE0R00X; Num Pins: 2; PART_SUBCLASS: RESISTORS; POWER: 1/16W; Part Class: RESISTORS; Price: 0; RESISTANCE: 0; RoHS Compliant: RoHS Compliant; Tolerance: ± 5%
R6006 R6106 = RESISTOR: RES_D,0402,30.1kOHM,1.00%,1/16W; Item Num: G21796-018; Lead Free Status: No; Manufacturer: YAGEO CORP.; Manufacturer Part Num: RC0402FR-0730K1P; Manufacturer's Part No.: RC0402FR-0730K1P; Num Pins: 2; Part Class: RESISTORS; Price: 0; RoHS Compliant: Yes; Tolerance: ± 1%
R6121 R6127 = RES_0_OHM_5%_1_16W_0402_SMD: RES D,0402,0.00 OHM,5.00%,1/16W; Item Num: A93549-001; Manufacturer: YAGEO CORP.; Manufacturer Part Num: RC0402JR-070RL; Tolerance: ± 5%
R6122 = RESISTOR: RES D,0402,0.00 OHM,5.00%,1/16W; Item Num: A93549-001; Lead Free Status: No; Manufacturer: Panasonic; Manufacturer Part Num: ERJ-2RKF1003X; Num Pins: 2; Part Class: Resistors; RoHS Compliant: Yes; Tolerance: ± 1%
R6123 R6129 R6137 = RESISTOR: RES D,0402,0.00 OHM,5.00%,1/16W; Item Num: A93549-001; Lead Free Status: No; Manufacturer: Panasonic; Manufacturer Part Num: ERJ-2RKF1003X; Num Pins: 2; Part Class: Resistors; Price: 0; RoHS Compliant: Yes
R6124 R6125 R6130 R6131 R6138 R6139 = RESISTOR: RES,100K OHMS,1.0%,1/16W,0402; Item Num: A78422-001; Lead Free Status: No; Manufacturer: Panasonic; Manufacturer Part Num: ERJ-2RKF1003X; Num Pins: 2; Part Class: Resistors; Price: 0; RoHS Compliant: Yes; Tolerance: ± 1%
R6128 R6141 = RESISTOR: RES D,0402,0.00 OHM,5.00%,1/16W; Item Num: A93549-001; Lead Free Status: No; Manufacturer: Panasonic; Manufacturer Part Num: ERJ-2RKF1003X; Num Pins: 2; Part Class: Resistors; RoHS Compliant: Yes; TOLERANCE: ± 1%
R6133 R6134 = RESISTOR: RES,4.70K OHMS,1.0%,1/16W,0402; Item Num: A93548-517; Lead Free Status: No; Manufacturer: Vishay; Manufacturer Part Num: CRCW04024K70FKED; Manufacturer's Part No.: ERJ-2GEJ472X; Num Pins: 2; Part Class: RESISTORS; Price: 0; RoHS Compliant: Yes; Tolerance: ± 1%
R2788 R6221-R6223 = RESISTOR: RES,10.0K OHMS,1.0%,1/16W, 0402; AGILE_LINK: http://sj-agile9app/Agile/PLMServlet?action=OpenEmailObject&classid=10000&objid=146548997; Item Num: K28115-001; LIFECYCLE_PHASE: Active; Lead Free Status: No; MFR_LIFECYCLE: Active; Manufacturer: Panasonic; Manufacturer Part Num: ERJ-2RKF1002X; Num Pins: 2; PART_SUBCLASS: RESISTORS; POWER: 1/16W; RESISTANCE: 10K; RoHS Compliant: Yes; TOLERANCE: ± 1%
ST23-ST27 ST29 = SHORT
TP983-TP992 TP994 TP998 TP999 TP1008 = TP,_0.016_,_Thru_Hole
U128 U133 U134 U142 = LTM4623EY#PBF: Item Num: K15502-001
C977 C986 C7422 = CAP: CAP CER 2.2UF 10V X6S 0402; Dielectric: X6S; Item Num: H90637-001; LIFECYCLE_PHASE: Active; Lead Free Status: Lead Free; Manufacturer: Murata; Manufacturer Part Num: GRM155C81A225KE44D; Num Pins: 2; Part Class: CAPACITORS; RATED_VOLTAGE: 10V; RoHS Compliant: RoHS Compliant; Tolerance: 10%
C978-C982 C984 C987-C996 C7423-C7432 = CAP: CAP CER 22UF 6.3V X6S 0603; AGILE_LINK: http://sj-agile9app/Agile/PLMServlet?action=OpenEmailObject&classid=10000&objid=257560276; Item Num: H63299-001; LIFECYCLE_PHASE: Active; Lead Free Status: Lead Free; MFR_LIFECYCLE: Active; Manufacturer: Murata; Manufacturer Part Num: GRM188C80J226ME15D; Num Pins: 2; PART_SUBCLASS: CAPACITORS; RATED_VOLTAGE: 6.3V; RoHS Compliant: RoHS Compliant; TOLERANCE: 20%; Temperature Coefficient: X6S
C983 C997 C7433 = CAP: CAPC,  X7R, 0402, 0.1uF, 25V, ±20%; Dielectric: X6S; Item Num: K13660-001; LIFECYCLE_PHASE: Active; Lead Free Status: Lead Free; Manufacturer: Murata; Manufacturer Part Num: GRM155R71E104KE14D; Num Pins: 2; Part Class: CAPACITORS; RATED_VOLTAGE: 25V; RoHS Compliant: RoHS Compliant; Tolerance: 10%
C985 C998 C7434 = CAP: CAP - CER, 10NF, 50V, +/-10%, X7R, 0402 SMD; CAPACITANCE: 0.1uF; Dielectric: X7R; Item Num: A36096-100; LIFECYCLE_PHASE: Active; Lead Free Status: Lead Free; Manufacturer: Murata; Manufacturer Part Num: GRM155R71H103KA88D; Num Pins: 2; Part Class: CAPACITORS; RATED_VOLTAGE: 50V; RoHS Compliant: RoHS Compliant; Tolerance: 10%
R815 R816 R818-R822 R824-R826 R2779 R2780 R2782-R2784 = RESISTOR: RES,10.0K OHMS,1.0%,1/16W, 0402; AGILE_LINK: http://sj-agile9app/Agile/PLMServlet?action=OpenEmailObject&classid=10000&objid=146548997; Item Num: K28115-001; LIFECYCLE_PHASE: Active; Lead Free Status: No; MFR_LIFECYCLE: Active; Manufacturer: Panasonic; Manufacturer Part Num: ERJ-2RKF1002X; Num Pins: 2; PART_SUBCLASS: RESISTORS; POWER: 1/16W; RESISTANCE: 10K; RoHS Compliant: Yes; TOLERANCE: 1%
R817 R823 R836 R2781 = RESISTOR: RES ZERO OHM 1/16W 5% 0402 SMD; Item Num: H30887-001; Lead Free Status: No; Manufacturer: Panasonic; Manufacturer Part Num: ERJ-2GE0R00X; Num Pins: 2; Part Class: RESISTORS; RoHS Compliant: Yes; Tolerance: 5%
U84 U85 U108 = TPS51200: IC,LIN,SOIC,TPS51200,VREG; Item Num: H28999-001; Manufacturer: TI
C1960 C7608 = CAP: CAPC,X6S,0402,1.00UF,25.00V,+/- 10%; Item Num: H81594-001; Lead Free Status: Yes; Manufacturer: Murata; Manufacturer Part Num: GRM155C81E105KE11D; Num Pins: 2; Part Class: CAPACITORS; RATED_VOLTAGE: 25V; RoHS Compliant: Yes
C1961 = CAP: CAP.,2.2uF,X7R,6.3V,20%,0603; CLASS: DISCRETE; Dielectric Type: X7R; FPLIST: CC0603N,CC0603L,CC0603M; Inventory Qty: 15202; Item Num: E54182-001; Manufacturer: kemet; Manufacturer PN: C1608X7R1A225M080AC; Manufacturer Part Num: C0603C225K9PAC; PART_NUMBER: 150-3503; Rated Voltage: 6.3V; Tolerance: 20%
C1962-C1964 C7610-C7612 = CAP: CAP CER 100UF 6.3V X6T 1206; AGILE_LINK: http://sj-agile9app/Agile/PLMServlet?action=OpenEmailObject&classid=10000&objid=257560276; Item Num: H65271-004; LIFECYCLE_PHASE: Active; Lead Free Status: Lead Free; MFR_LIFECYCLE: Active; Manufacturer: Murata; Manufacturer Part Num: GRM31CD80J107ME39L; Num Pins: 2; PART_SUBCLASS: CAPACITORS; RATED_VOLTAGE: 6.3V; RoHS Compliant: RoHS Compliant; TOLERANCE: 20%; Temperature Coefficient: X6T
C1966 C7614 = CAP: CAP CER 0.1UF 25V X6S 0402; CAPACITANCE: 0.1uF; Dielectric: X6S; Item Num: K19434-001; LIFECYCLE_PHASE: Active; Lead Free Status: Lead Free; Manufacturer: Murata; Manufacturer Part Num: GRM155C81E104KA12D; Num Pins: 2; Part Class: CAPACITORS; RATED_VOLTAGE: 25V; RoHS Compliant: RoHS Compliant; Tolerance: 10%
C1967 C7615 = CAP: CAP CER 0.1UF 25V X6S 0402; Dielectric: X6S; Item Num: K19434-001; LIFECYCLE_PHASE: Active; Lead Free Status: Lead Free; Manufacturer: Murata; Manufacturer Part Num: GRM155C81E104KA12D; Num Pins: 2; Part Class: CAPACITORS; RATED_VOLTAGE: 25V; RoHS Compliant: RoHS Compliant; Tolerance: 10%
C7715 C7716 = Cap,_NP,_0402: CAP, CERAMIC, 100pF, 0402, 5%, 50VDC, NPO; Item Num: A36095-026; Manufacturer: Murata; Manufacturer Part Num: GRM1555C1H101JZ01D; RATED_VOLTAGE: 50V
C7721 = Cap,_NP,_0402: CAP,0402,10PF,50V,5%; Item Num: C17122-001; Manufacturer: KEMET; Manufacturer Part Num: C0402C100J5GACTU; RATED_VOLTAGE: 50V
R6043 R6088 = RESISTOR: RES 100 OHM 1/16W .1% 0402,; Item Num: G61554-001; Lead Free Status: No; Manufacturer: PANASONIC INDUSTRIAL; Manufacturer Part Num: ERA-2AEB101X; Num Pins: 2; Package: 0402; Part Class: RESISTORS; Part Number: ERA-2AEB101X; Price: 0; RoHS Compliant: Yes; Tolerance: ± 0.1%
R6044 R6089 = Resistor,_0402: RES, 100K OHMS, 1.0%, 1/10W, 0402; Item Num: E86804-001; Manufacturer: Panasonic; Manufacturer Part Num: ERJ-2RKF1003X; Tolerance: ± 1%
R6045 R6090 = RESISTOR: RES,10.0K OHMS,1.0%,1/16W, 0402; AGILE_LINK: http://sj-agile9app/Agile/PLMServlet?action=OpenEmailObject&classid=10000&objid=146548997; Item Num: A93548-034; LIFECYCLE_PHASE: Active; Lead Free Status: No; MFR_LIFECYCLE: Active; Manufacturer: Panasonic; Manufacturer Part Num: ERJ-2RKF1002X; Num Pins: 2; PART_SUBCLASS: RESISTORS; POWER: 1/16W; RESISTANCE: 10.0K; RoHS Compliant: Yes; TOLERANCE: ± 1%
R6079 R6084 = RESISTOR: RES ZERO OHM 1/16W 5% 0402 SMD; Altera Part No.: P02-14020R; Item Num: H30887-001; Lead Free Status: No; Manufacturer: Panasonic; Manufacturer Part Num: ERJ-2GE0R00X; Num Pins: 2; Part Class: RESISTORS; Price: 0; RoHS Compliant: Yes; Tolerance: ± 5%
R6080 R6085 = RESISTOR: RES ZERO OHM 1/16W 5% 0402 SMD; Item Num: H30887-001; Lead Free Status: No; Manufacturer: Panasonic; Manufacturer Part Num: ERJ-2GE0R00X; Num Pins: 2; Part Class: RESISTORS; RoHS Compliant: Yes; Tolerance: ± 5%
R6081 R6086 R6173 = RESISTOR: RES,4.70K OHMS,1.0%,1/16W,0402; Item Num: D60468-001; Lead Free Status: No; Manufacturer: Vishay; Manufacturer Part Num: CRCW04024K70FKED; Manufacturer's Part No.: ERJ-2GEJ472X; Num Pins: 2; Part Class: RESISTORS; Price: 0; RoHS Compliant: Yes; Tolerance: ± 1%
R6082 = RESISTOR: RES SMD 15K OHM 0.1% 1/10W 0402; Altera Part No.: P02-14020R; Item Num: J59798-001; Lead Free Status: No; Manufacturer: Panasonic; Manufacturer Part Num: ERA2AEB153X; Num Pins: 2; Part Class: RESISTORS; Part Number: ERJ-2RKF1502X; Price: 0; RoHS Compliant: Yes; Tolerance: ± 1%
U138 U139 = LTM4643EY#PBF: IC, ULTRATHIN QUAD uMODULE REGULATOR, WITH CONFIGURABLE 3A OUTPUT ARRAY, BGA-77P, SMD; Item Num: M75351-001
C7609 = CAP: CAP C, 0603, 2.2uF 6.3V, X5R; CLASS: DISCRETE; FPLIST: CC0603N,CC0603L,CC0603M; Inventory Qty: 15202; Item Num: E54182-001; Manufacturer: kemet; Manufacturer PN: C1608X7R1A225M080AC; Manufacturer Part Num: C0603C225K9PAC; PART_NUMBER: 150-3503; Rated Voltage: 10V; Tolerance: 20%
C7722 = Cap,_NP,_0402: CAP,0402,10PF,50V,5%; Item Num: C17122-001; Manufacturer: Murata; Manufacturer Part Num: C0402C100J5GACTU; Part Number: C0402C100J5GACTU; RATED_VOLTAGE: 50V
R6087 = RESISTOR: RES SMD 15K OHM 0.1% 1/10W 0402; Altera Part No.: P02-14020R; Item Num: J59798-001; Lead Free Status: No; Manufacturer: Panasonic; Manufacturer Part Num: ERJ-2RKF1502X; Num Pins: 2; Part Class: RESISTORS; Part Number: ERJ-2RKF1502X; Price: 0; RoHS Compliant: Yes; Tolerance: ± 1%
C1004 = PCAP: CAP - POSCAP 100uF, 6.3V, ESR =.025 OHMS, B2; Item Num: 724613-168; LIFECYCLE_PHASE: Active; Lead Free Status: Lead Free; MFR_LIFECYCLE: Active; Manufacturer: Panasonic; Manufacturer Part Num: 6TPE100MPB; Num Pins: 2; PART_SUBCLASS: CAPACITORS; RATED_VOLTAGE: 6.3V; RoHS Compliant: RoHS Compliant; Working Voltage: 6.3V
C1005 = PCAP: CAP DNI 1210; AGILE_LINK: http://sj-agile9app/Agile/PLMServlet?action=OpenEmailObject&classid=10000&objid=14603863; LIFECYCLE_PHASE: Active; MFR_LIFECYCLE: Active; Num Pins: 2; PART_SUBCLASS: CAPACITORS
C1006 = CAP_NP: CAP CER 47000PF 25V X7R 0402; AGILE_LINK: http://sj-agile9app/Agile/PLMServlet?action=OpenEmailObject&classid=10000&objid=215383831; CAPACITANCE: 47000pF; Item Num: J98424-001; LIFECYCLE_PHASE: Preliminary; Manufacturer: Murata; Manufacturer Part Num: GRM155R71E473KA88D; Num Pins: 2; PART_SUBCLASS: CAPACITORS; RATED_VOLTAGE: 25V; TOLERANCE: +/-10%
C7439 = CAP: CAP - CER, 10NF, 50V, +/-10%, X7R, 0402 SMD; CAPACITANCE: 0.1uF; Item Num: A36096-100; LIFECYCLE_PHASE: Active; Lead Free Status: Lead Free; MFR_LIFECYCLE: Active; Manufacturer: Murata; Manufacturer Part Num: GRM155R71H103KA88D; Num Pins: 2; PART_SUBCLASS: CAPACITORS; Part Class: CAPACITORS; RATED_VOLTAGE: 50V; RoHS Compliant: RoHS Compliant; Tolerance: +/-10%
C7526 C7650 C7777 = CAP: CAPC,X6S,0402,1.00UF,25.00V,+/- 10%; IPN: xxxxxx-xxx; Item Num: H81594-001; Lead Free Status: Yes; Manufacturer: Murata; Manufacturer Part Num: GRM155C81E105KE11D; Num Pins: 2; Part Class: CAPACITORS; RATED_VOLTAGE: 25V; RoHS Compliant: Yes; Temperature Coefficient: X6S; Voltage: 25V
R835 = RESISTOR: RES SMD 0 OHM JUMPER 3/4W 1206; AGILE_LINK: http://sj-agile9app/Agile/PLMServlet?action=OpenEmailObject&classid=10000&objid=146548997; Item Num: A93552-015; LIFECYCLE_PHASE: Active; Lead Free Status: No; MFR_LIFECYCLE: Active; Manufacturer: Vishay Dale; Manufacturer Part Num: CRCW12060000Z0EAHP; Num Pins: 2; PART_SUBCLASS: RESISTORS; POWER: 3/4W; RESISTANCE: 0; RoHS Compliant: Yes; TOLERANCE: +/-1%
R837 R840 = RESISTOR: RES 4.7K OHM 1/16W 5% 0402 SMD; Item Num: A93549-020; Lead Free Status: No; Manufacturer: Panasonic; Manufacturer Part Num: ERJ-2GEJ472X; Manufacturer's Part No.: ERJ-2GEJ472X; Num Pins: 2; Part Class: RESISTORS; Price: 0; RoHS Compliant: Yes
R838 = RESISTOR: RES ZERO OHM 1/16W 5% 0402 SMD; Altera Part No.: P02-14020R; Item Num: H30887-001; Lead Free Status: No; Manufacturer: Panasonic; Manufacturer Part Num: ERJ-2GE0R00X; Num Pins: 2; Part Class: RESISTORS; Price: 0; RoHS Compliant: Yes; Tolerance: 5%
R839 = RES_0_OHM_5%_1_16W_0402_SMD: Item Num: H30887-001
R2785 = RESISTOR: RES 19.1K 1% 1/16W 0402; Item Num: L14017-001; Lead Free Status: No; Manufacturer: Panasonic; Manufacturer Part Num: ERJ-2RKF1912X; Manufacturer's Part No.: ERJ-2GEJ472X; Num Pins: 2; Part Class: RESISTORS; Price: 0; RoHS Compliant: Yes; TOLERANCE: ± 1%
R2786 = RESISTOR: RES ZERO OHM 1/16W 5% 0402 SMD; Altera Part No.: P02-14020R; Item Num: H30887-001; LIFECYCLE_PHASE: Active; Lead Free Status: No; MFR_LIFECYCLE: Active; Manufacturer: Panasonic; Manufacturer Part Num: ERJ-2GE0R00X; Num Pins: 2; PART_SUBCLASS: RESISTORS; POWER: 1/16W; Part Class: RESISTORS; Price: 0; RESISTANCE: 0; RoHS Compliant: RoHS Compliant; Tolerance: +/-5%
R6142 = RESISTOR: RES D,0402,0.00 OHM,5.00%,1/16W; Item Num: A93549-001; Lead Free Status: No; Manufacturer: Panasonic; Manufacturer Part Num: ERJ-2RKF1003X; Num Pins: 2; Part Class: Resistors; Price: 0; RoHS Compliant: Yes; TOLERANCE: ± 1%
R6143 R6144 = RESISTOR: RES,100K OHMS,1.0%,1/16W,0402; Item Num: A78422-001; Lead Free Status: No; Manufacturer: Panasonic; Manufacturer Part Num: ERJ-2RKF1003X; Num Pins: 2; Part Class: Resistors; Price: 0; RoHS Compliant: Yes; TOLERANCE: ± 1%
R6171 = RESISTOR: RES D,0402,0.00 OHM,5.00%,1/16W; Altera Part No.: P02-14020R; Item Num: A93549-001; Lead Free Status: No; Manufacturer: YAGEO CORP.; Manufacturer Part Num: RC0402JR-070RL; Num Pins: 2; Part Class: RESISTORS; Price: 0; RoHS Compliant: Yes; Tolerance: 5%
R6004 R6172 = RESISTOR: RES D,0402,0.00 OHM,5.00%,1/16W; Altera Part No.: P02-14020R; Item Num: A93549-001; LIFECYCLE_PHASE: Active; Lead Free Status: No; MFR_LIFECYCLE: Active; Manufacturer: YAGEO CORP.; Manufacturer Part Num: RC0402JR-070RL; Num Pins: 2; PART_SUBCLASS: RESISTORS; POWER: 1/16W; Part Class: RESISTORS; RoHS Compliant: RoHS Compliant; Tolerance: ± 5%
U87 = FDMC8878_VER2: MOSFET N-CHANNEL DUAL COOL PWR TRENCH 40A 25V 3.5mOHM; Item Num: K14521-001; Manufacturer: Fairchild Semiconductor
U88 = LTC4365_DFN: IC - LT4365-1, DFN8, UV, OV, REVERSE SUPPLY PROTECTION, VIN=2.5V-34V, (3 X 2 X 0.75)MM, TEMP=-40C-125C; Item Num: K64807-001; LIFECYCLE_PHASE: Active; Lead Free Status: Lead Free; MFR_LIFECYCLE: Active; Manufacturer: Linear Technology; Manufacturer Part Num: LTC4365HDDB-1#TRMPBF; Num Pins: 9; PART_SUBCLASS: ICS; RoHS Compliant: RoHS Compliant
C1309 = CAP: CAP - CERAMIC, SMD/SMT 0805 25VDC 10uF 10% X5R; Item Num: H48130-001; Lead Free Status: No; Manufacturer: TDK Electronics; Manufacturer Part Num: TMK212BBJ106KGHT; Manufacturer's Part No.: TMK212BBJ106KGHT; Num Pins: 2; Part Class: CAPACITORS; RATED_VOLTAGE: 25V; RoHS Compliant: Yes
C1310 C1312 = CAP: CAP CER 0.1UF 25V 20% X7R 0402; Dielectric: X7R; Item Num: A36096-112; Manufacturer: Yageo; Manufacturer Part Num: CC0402KRX7R8BB104; Num Pins: 2; PART_SUBCLASS: CAPACITORS; Part Class: CAPACITORS; RATED_VOLTAGE: 25V; Tolerance: 10%
C1311 = CAP: SMD/SMT 10uF 10% 16Volts  0805; Item Num: K13661-001; Lead Free Status: No; Manufacturer: TDK Electronics; Manufacturer Part Num: C2012X5R1C106K085AC; Manufacturer's Part No.: ECJ-2FB1A106K; Num Pins: 2; Part Class: CAPACITORS; RATED_VOLTAGE: 16V; RoHS Compliant: Yes
C1313 = CAP: CAP - CER 4.7UF, +/-20%, 6.3V, X5R, 0402; Item Num: A36096-107; Manufacturer: Murata; Manufacturer Part Num: GRM155R60J475ME87D; RATED_VOLTAGE: 6.3V; Tolerance: +/-20%; Voltage: 6.3V
C7518 = CAP: CAP - CER, 10NF, 50V, +/-10%, X7R, 0402 SMD; CAPACITANCE: 0.1uF; Item Num: A36096-100; LIFECYCLE_PHASE: Active; Lead Free Status: Lead Free; MFR_LIFECYCLE: Active; Manufacturer: Murata; Manufacturer Part Num: GRM155R71H103KA88D; Num Pins: 2; PART_SUBCLASS: CAPACITORS; Part Class: CAPACITORS; RATED_VOLTAGE: 50V; RoHS Compliant: RoHS Compliant; Tolerance: +/-10$
FB40 = BEAD_FERRITE_SM: IND - SMD EMI FILTERS/CHIP FERRITE BEAD, 220-OHM @ 100MHZ, 0.35-OHM DCR, 0402; Imax (A): 300mA; Item Num: G79186-002; Manufacturer: Wurth Elektronik; Manufacturer Part Num: 742792780; Rdc (Ohms): 350mOhm; Tolerance (%): 25%
R916 = RESISTOR: RES,4.70K OHMS,1.0%,1/16W,0402; IPN: xxxxxx-xxx; Item Num: A93548-517; Lead Free Status: No; Manufacturer: Vishay; Manufacturer Part Num: CRCW04024K70FKED; Manufacturer's Part No.: ERJ-2GEJ472X; Num Pins: 2; Part Class: RESISTORS; Price: 0; RoHS Compliant: Yes; TOLERANCE: ±1%
R917 = RES_0_OHM_5%_1_16W_0402_SMD: Item Num: H30887-001; TOLERANCE: ±5%
R918 = RESISTOR: RES D,0402,0.00 OHM,5.00%,1/16W; Altera Part No.: P02-14020R; IPN: xxxxxx-xxx; Item Num: A93549-001; Lead Free Status: No; Manufacturer: Panasonic; Manufacturer Part Num: ERJ-2GE0R00X; Num Pins: 2; Part Class: RESISTORS; Price: 0; RoHS Compliant: Yes; Tolerance: 5%
R920 R923 = RESISTOR: RES,100K OHMS,1.0%,1/16W,0402; IPN: xxxxxx-xxx; Item Num: A93548-128; Lead Free Status: No; Manufacturer: Vishay; Manufacturer Part Num: CRCW0402100KFKED; Num Pins: 2; Part Class: Resistors; Price: 0; RoHS Compliant: Yes; TOLERANCE: ±1%
R921 = RESISTOR: RES,10.0K OHMS,1.0%,1/16W, 0402; AGILE_LINK: http://sj-agile9app/Agile/PLMServlet?action=OpenEmailObject&classid=10000&objid=146548997; Item Num: K28115-001; LIFECYCLE_PHASE: Active; Lead Free Status: No; MFR_LIFECYCLE: Active; Manufacturer: Panasonic; Manufacturer Part Num: ERJ-2RKF1002X; Num Pins: 2; PART_SUBCLASS: RESISTORS; POWER: 1/16W; RoHS Compliant: Yes; TOLERANCE: ±1%
R925 = RESISTOR: RES D,0402,66.50 kOHM,1.00%,1/16W,YES; IPN: xxxxxx-xxx; Item Num: A93548-286; Lead Free Status: No; Manufacturer: Vishay; Manufacturer Part Num: CRCW04026652FKED; Num Pins: 2; Part Class: Resistors; Price: 0; RoHS Compliant: Yes; TOLERANCE: ±1%
R6003 = RESISTOR: RES D,0402,0.00 OHM,5.00%,1/16W; Altera Part No.: P02-14020R; Item Num: A93549-001; Lead Free Status: No; Manufacturer: YAGEO CORP.; Manufacturer Part Num: RC0402JR-070RL; Num Pins: 2; Part Class: RESISTORS; Price: 0; RoHS Compliant: Yes; Tolerance: ± 5%
R6005 = RESISTOR: RES 4.7K OHM 1/16W 5% 0402 SMD; Item Num: A93549-020; Lead Free Status: No; Manufacturer: Panasonic; Manufacturer Part Num: ERJ-2GEJ472X; Manufacturer's Part No.: ERJ-2GEJ472X; Num Pins: 2; Part Class: RESISTORS; Price: 0; RoHS Compliant: Yes; Tolerance: ± 5%
R6136 = RESISTOR: RES D,0402,0.00 OHM,5.00%,1/16W; Item Num: A93549-001; Lead Free Status: No; Manufacturer: Panasonic; Manufacturer Part Num: ERJ-2RKF1003X; Num Pins: 2; Part Class: Resistors; RoHS Compliant: Yes; Tolerance: ± 5%
U132 = LT3042IDD#PBF_0: LDO,20VIN 200MA ULTRA LO NOISE,RF LINEAR REGULATOR; Item Num: M21823-001; Manufacturer: Analog Devices

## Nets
5V: C7521.2 C7636.2 C7648.2 C7649.2 C7778.2 C7779.2 R836.1 R6121.1 R6127.1 R6133.2 R6134.2 U128.D5(VIN1) U128.E5(VIN2) U142.D5(VIN1) U142.E5(VIN2) ; also on sheet 48 57 59 65
12V_G2: C1958.2 C1959.2 C1960.1 C7517.2 C7526.1 C7606.2 C7607.2 C7608.1 C7667.2 C7668.2 C7674.2 C7777.1 FB40.1 U133.C5(SVIN) U133.D5(VIN1) U133.E5(VIN2) U134.C5(SVIN) U134.D5(VIN1) U134.E5(VIN2) U138.B3(VIN1_1) U138.B4(VIN1_2) U138.B5(SVIN1) U138.E3(VIN2_1) U138.E4(VIN2_2) U138.E5(SVIN2) U138.H3(VIN3_1) U138.H4(VIN3_2) U138.H5(SVIN3) U138.L3(VIN4_1) U138.L4(VIN4_2) U138.L5(SVIN4) U139.B3(VIN1_1) U139.B4(VIN1_2) U139.B5(SVIN1) U139.E3(VIN2_1) U139.E4(VIN2_2) U139.E5(SVIN2) U139.H3(VIN3_1) U139.H4(VIN3_2) U139.H5(SVIN3) U139.L3(VIN4_1) U139.L4(VIN4_2) U139.L5(SVIN4) ; also on sheet 53 57 58 59 60 61 62 63 64 65 66 67
AGND_1p2V_PRE: C7644.2 R6012.1 ST23.1
AGND_1p8V_PRE: C7645.2 R6106.1 ST29.1
AGND_VCCFUSEWR_SDM: C7651.2 R6006.1 ST24.1
GND: C977.1 C978.2 C979.2 C980.2 C981.2 C982.2 C983.2 C984.2 C985.2 C986.1 C987.2 C988.2 C989.2 C990.2 C991.2 C992.2 C993.2 C994.2 C995.2 C996.2 C997.2 C998.2 C1004.2 C1005.2 C1006.2 C1309.1 C1310.2 C1311.1 C1312.2 C1313.2 C1958.1 C1959.1 C1960.2 C1961.2 C1962.1 C1963.1 C1964.1 C1967.1 C7422.1 C7423.2 C7424.2 C7425.2 C7426.2 C7427.2 C7428.2 C7429.2 C7430.2 C7431.2 C7432.2 C7433.2 C7434.2 C7439.1 C7517.1 C7518.1 C7519.1 C7520.1 C7521.1 C7522.1 C7523.1 C7524.1 C7526.2 C7606.1 C7607.1 C7608.2 C7609.2 C7610.1 C7611.1 C7612.1 C7615.1 C7636.1 C7637.1 C7638.1 C7639.1 C7648.1 C7649.1 C7650.2 C7653.1 C7666.1 C7667.1 C7668.1 C7674.1 C7703.1 C7704.1 C7708.1 C7709.1 C7712.1 C7714.1 C7777.2 C7778.1 C7779.1 R818.1 R820.2 R824.1 R826.2 R840.1 R916.1 R917.2 R921.1 R925.1 R2782.1 R2784.2 R2786.1 R6002.1 R6005.1 R6008.1 R6043.2 R6088.2 R6104.1 R6173.1 ST23.2 ST24.2 ST25.2 ST26.2 ST27.2 ST29.2 U84.4(PGND) U84.8(GND) U84.11(MPAD) U85.4(PGND) U85.8(GND) U85.11(MPAD) U88.1(GND) U88.2(OV) U88.9(GND) U108.4(PGND) U108.8(GND) U108.11(MPAD) U128.B3(GND) U128.B4(SGND) U128.C3(GND) U128.D3(GND) U128.D4(GND) U128.E3(GND) U132.8(GND) U132.11(GND_PAD) U133.B3(GND) U133.B4(SGND) U133.C3(GND) U133.D3(GND) U133.D4(GND) U133.E3(GND) U134.B3(GND) U134.B4(SGND) U134.C3(GND) U134.D3(GND) U134.D4(GND) U134.E3(GND) U138.A4(GND) U138.A5(GND) U138.B1(GND) U138.B2(GND) U138.C5(GND) U138.D3(GND) U138.D4(GND) U138.D5(GND) U138.E1(GND) U138.E2(GND) U138.F5(GND) U138.G3(GND) U138.G4(GND) U138.G5(GND) U138.H1(GND) U138.H2(GND) U138.J5(GND) U138.K3(GND) U138.K4(GND) U138.L1(GND) U138.L2(GND) U139.A4(GND) U139.A5(GND) U139.B1(GND) U139.B2(GND) U139.C5(GND) U139.D3(GND) U139.D4(GND) U139.D5(GND) U139.E1(GND) U139.E2(GND) U139.F5(GND) U139.G3(GND) U139.G4(GND) U139.G5(GND) U139.H1(GND) U139.H2(GND) U139.J5(GND) U139.K3(GND) U139.K4(GND) U139.L1(GND) U139.L2(GND) U142.B3(GND) U142.B4(SGND) U142.C3(GND) U142.D3(GND) U142.D4(GND) U142.E3(GND) ; also on sheet 9 10 11 13 14 15 16 17 18 19 20 21 22 23 25 26 27 28 29 30 31 32 33 34 35 36 38 39 40 41 42 43 44 45 46 47 48 49 50 51 52 53 54 55 56 57 58 59 60 61 62 63 64 65 66 67 74 75 76 77
VCCE_PLL_DTS_GXR: C1311.2 C1312.1 R923.2 TP985.1 U132.9(OUTS) U132.10(OUT) ; also on sheet 38
VCCEPLL_EN: R916.2 R918.1 U132.3(EN) ; also on sheet 51
VCCEPLL_PG: R920.1 U132.4(PG) ; also on sheet 49
VCCFUSEWR_EN: R6004.2 ; also on sheet 50
VCCFUSEWR_PG: R6223.2 U133.C2(PGOOD) ; also on sheet 50
VCCFUSEWR_SDM: C7519.2 C7520.2 C7711.2 C7712.2 TP986.1 U133.C1(VOUT1) U133.D1(VOUT2) U133.D2(VOUT3) U133.E1(VOUT4) U133.E2(VOUT5) ; also on sheet 39 76
0p6V_VREF_DDR4_CH01: C983.1 TP990.1 U84.6(REFOUT) ; also on sheet 9 10 11 14 15 16 39 76
0p6V_VREF_DDR4_CH2: C997.1 TP992.1 U85.6(REFOUT) ; also on sheet 20 39 76
0p6V_VREF_DDR4_CH3: C7433.1 TP999.1 U108.6(REFOUT) ; also on sheet 19 39 76
0p6V_VTT_DDR4_CH01: C978.1 C979.1 C980.1 C984.1 TP989.1 U84.3(VO) U84.5(VOSNS) ; also on sheet 11 16
0p6V_VTT_DDR4_CH2: C987.1 C988.1 C989.1 C990.1 C991.1 C992.1 C995.1 C996.1 TP991.1 U85.3(VO) U85.5(VOSNS) ; also on sheet 20
0p6V_VTT_DDR4_CH3: C7423.1 C7424.1 C7425.1 C7426.1 C7427.1 C7428.1 C7431.1 C7432.1 TP998.1 U108.3(VO) U108.5(VOSNS) ; also on sheet 19
1p2V_DDR4_CH01: C981.1 C982.1 C1961.1 C1962.2 C1963.2 C1964.2 C7715.1 R819.2 TP987.1 U84.2(VLDOIN) U138.A1(VOUT1_1) U138.A2(VOUT1_2) U138.A3(VOUT1_3) U138.C1(VOUT2_1) U138.D1(VOUT2_2) U138.D2(VOUT2_3) U138.F1(VOUT3_1) U138.G1(VOUT3_2) U138.G2(VOUT3_3) U138.J1(VOUT4_1) U138.K1(VOUT4_2) U138.K2(VOUT4_3) ; also on sheet 9 10 11 14 15 16 32 39 46 47 52 76 77
1p2V_DDR4_CH01_AGND: C1966.1 C7721.2 R6081.1 ST25.1 U138.F7(SGND)
1p2V_DDR4_CH1_EN: R6080.2 ; also on sheet 51
1p2V_DDR4_CH01_PG: R6045.1 U138.C3(PGOOD1) ; also on sheet 51
1p2V_DDR4_CH2: C993.1 C994.1 C7429.1 C7430.1 C7609.1 C7610.2 C7611.2 C7612.2 C7716.1 R825.2 R2783.2 TP988.1 U85.2(VLDOIN) U108.2(VLDOIN) U139.A1(VOUT1_1) U139.A2(VOUT1_2) U139.A3(VOUT1_3) U139.C1(VOUT2_1) U139.D1(VOUT2_2) U139.D2(VOUT2_3) U139.F1(VOUT3_1) U139.G1(VOUT3_2) U139.G2(VOUT3_3) U139.J1(VOUT4_1) U139.K1(VOUT4_2) U139.K2(VOUT4_3) ; also on sheet 19 20 30 39 76
1P2V_DDR4_CH2_AGND: C7614.1 C7722.2 R6086.1 ST26.1 U139.F7(SGND)
1p2V_DDR4_CH2_EN: R6085.2 ; also on sheet 51
1p2V_DDR4_CH2_PG: R6090.1 U139.C3(PGOOD1) ; also on sheet 50
1p2V_PRE: C7523.2 C7524.2 C7707.2 C7708.2 TP984.1 U128.C1(VOUT1) U128.D1(VOUT2) U128.D2(VOUT3) U128.E1(VOUT4) U128.E2(VOUT5) ; also on sheet 51
1p8V_PRE: C7638.2 C7639.2 C7706.2 C7709.2 TP983.1 U142.C1(VOUT1) U142.D1(VOUT2) U142.D2(VOUT3) U142.E1(VOUT4) U142.E2(VOUT5) ; also on sheet 35 49 50 51
2p5V: C7653.2 C7666.2 C7725.2 TP1008.1 U134.C1(VOUT1) U134.D1(VOUT2) U134.D2(VOUT3) U134.E1(VOUT4) U134.E2(VOUT5) ; also on sheet 9 10 11 14 15 16 19 20 43 45 46
2p5V_AGND: C7652.2 R2785.1 ST27.1
2p5V_EN: R6172.2 ; also on sheet 51
2p5V_PG: R2788.1 U134.C2(PGOOD) ; also on sheet 50
3p3V: C977.2 C986.2 C7422.2 R815.1 R816.1 R821.1 R822.1 R835.1 R838.2 R918.2 R920.2 R2779.1 R2780.1 R6003.1 R6044.2 R6045.2 R6079.2 R6084.2 R6089.2 R6090.2 R6171.1 U84.10(VIN) U85.10(VIN) U87.5(D) U88.3(UV) U108.10(VIN) ; also on sheet 54 58 59 63 65 66 67 74
CH01_RUN: C1966.2 R6079.1 R6080.1 R6081.2 U138.C6(RUN1) U138.F6(RUN2) U138.J6(RUN3) U138.K7(RUN4)
CH02_RUN: C7614.2 R6084.1 R6085.1 R6086.2 U139.C6(RUN1) U139.F6(RUN2) U139.J6(RUN3) U139.K7(RUN4)
IO_3p3V: C1004.1 C1005.1 R835.2 TP994.1 U87.1(S1) U87.2(S2) U87.3(S3) U88.6(VOUT) ; also on sheet 25 26 27 30 31 32 43 44 46 47 48 52
IO_3p3V_EN: R839.2 ; also on sheet 51
LTM4623_INTVCC: C7650.1 R2788.2 R6141.2 U134.E4(INTVCC)
LTM4623_INTVCC3: C7703.2 R6128.1 R6221.1 U142.E4(INTVCC)
LTM4623_INTVCC4: C7704.2 R6122.2 R6222.1 U128.E4(INTVCC)
LTM4623_INTVCC5: C7714.2 R6136.2 R6223.1 U133.E4(INTVCC)
VTT_DDR4_CH1_EN: R817.2 ; also on sheet 51
VTT_DDR4_CH2_EN: R823.2 ; also on sheet 51
VTT_DDR4_CH3_EN: R2781.2 ; also on sheet 51
N36315991: R815.2 U84.9(PGOOD)
N36316045: R816.2 R817.1 R818.2 U84.7(EN)
N36316148: C985.1 R819.1 R820.1 U84.1(REFIN)
N36316409: R821.2 U85.9(PGOOD)
N36316465: R822.2 R823.1 R824.2 U85.7(EN)
N36316589: C998.1 R825.1 R826.1 U85.1(REFIN)
N36348634: R837.1 U87.4(G) U88.5(GATE)
N36348657: R836.2 U88.4(VIN)
N36348739: R838.1 R839.1 R840.2 U88.8(~{SHDN})
N47056010: R2779.2 U108.9(PGOOD)
N47056063: R2780.2 R2781.1 R2782.2 U108.7(EN)
N47056195: C7434.1 R2783.1 R2784.1 U108.1(REFIN)
N47813492: R6008.2 U128.A4(FREQ)
N47813514: C7522.2 U128.A2(TRACK/SS)
N47814473: C1309.2 C1310.1 FB40.2 U132.1(IN1) U132.2(IN2)
N47814553: R923.1 R925.2 U132.6(PGFB)
N47814610: C1313.1 R921.2 U132.7(SET)
N47814650: R917.1 U132.5(ILIM)
N47815277: R6002.2 U133.A4(FREQ)
N47815307: R6003.2 R6004.1 R6005.2 U133.A3(RUN)
N47815315: C7518.2 U133.A2(TRACK/SS)
N47816801: R2786.2 U134.A4(FREQ)
N47816829: R6171.2 R6172.1 R6173.2 U134.A3(RUN)
N47816837: C7439.2 U134.A2(TRACK/SS)
N47816940: C7725.1 R2785.2 U134.B1(FB)
N48264639: C7715.2 R6082.2 U138.A7(FB1) U138.D7(FB2) U138.G7(FB3) U138.J7(FB4)
N48264690: C7721.1 U138.B7(COMP1) U138.E7(COMP2) U138.H7(COMP3) U138.L7(COMP4)
N48264694: U138.B6(MODE1) U138.C4(INTVCC1)
N48264698: C1967.2 U138.A6(TRACK/SS1) U138.D6(TRACK/SS2) U138.G6(TRACK/SS3) U138.K6(TRACK/SS4)
N48264773: U138.E6(MODE2) U138.F4(INTVCC2)
N48264853: U138.H6(MODE3) U138.J4(INTVCC3)
N48264943: U138.K5(INTVCC4) U138.L6(MODE4)
N48264979: R6043.1 R6082.1
N48265099: R6044.1 U138.F3(TEMP)
N48270066: C7716.2 R6087.2 U139.A7(FB1) U139.D7(FB2) U139.G7(FB3) U139.J7(FB4)
N48270081: C7722.1 U139.B7(COMP1) U139.E7(COMP2) U139.H7(COMP3) U139.L7(COMP4)
N48270093: U139.B6(MODE1) U139.C4(INTVCC1)
N48270097: C7615.2 U139.A6(TRACK/SS1) U139.D6(TRACK/SS2) U139.G6(TRACK/SS3) U139.K6(TRACK/SS4)
N48270166: U139.E6(MODE2) U139.F4(INTVCC2)
N48270246: U139.H6(MODE3) U139.J4(INTVCC3)
N48270336: U139.K5(INTVCC4) U139.L6(MODE4)
N48270376: R6087.1 R6088.1
N48287444: R6104.2 U142.A4(FREQ)
N48287466: C7637.2 U142.A2(TRACK/SS)
N48784258: R6121.2 U128.C5(SVIN)
N48784266: R6122.1 R6123.2 R6124.1 R6125.1
N48784300: C7644.1 R6123.1 U128.A1(COMP)
N48784323: R6124.2 U128.B2(PHMODE)
N48784335: R6125.2 U128.C4(MODE)
N48786358: R6127.2 U142.C5(SVIN)
N48786366: R6128.2 R6129.2 R6130.1 R6131.1
N48786400: C7645.1 R6129.1 U142.A1(COMP)
N48786423: R6130.2 U142.B2(PHMODE)
N48786435: R6131.2 U142.C4(MODE)
N48792865: R6133.1 U128.A3(RUN)
N48792977: R6134.1 U142.A3(RUN)
N48794434: R6136.1 R6137.2 R6138.1 R6139.1
N48794462: C7651.1 R6137.1 U133.A1(COMP)
N48794485: R6138.2 U133.B2(PHMODE)
N48794497: R6139.2 U133.C4(MODE)
N48795285: C7652.1 R6142.1 U134.A1(COMP)
N48795308: R6143.2 U134.B2(PHMODE)
N48795320: R6144.2 U134.C4(MODE)
N48795608: R6141.1 R6142.2 R6143.1 R6144.1
N48797862: C7706.1 R6106.2 U142.B1(FB)
N48798047: C7707.1 R6012.2 U128.B1(FB)
N48798268: C7711.1 R6006.2 U133.B1(FB)
N49586047: R6089.1 U139.F3(TEMP)
N49667985: R6221.2 U142.C2(PGOOD)
N49668581: R6222.2 U128.C2(PGOOD)
N50730400: C1006.1 R837.2

Not connected (* = marked no-connect by the designer): U88 7(~{FAULT})*; U128 A5(CLKIN)* B5(CLKOUT)*; U133 A5(CLKIN)* B5(CLKOUT)*; U134 A5(CLKIN)* B5(CLKOUT)*; U138 C2(PGOOD2)* C7(CLKIN)* F2(PGOOD3)* J2(PGOOD4)* J3(CLKOUT)*; U139 C2(PGOOD2)* C7(CLKIN)* F2(PGOOD3)* J2(PGOOD4)* J3(CLKOUT)*; U142 A5(CLKIN)* B5(CLKOUT)*

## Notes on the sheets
sheet 68
- PWR - 1p8V_PRE,1p2V_PRE
- Connect the input
  cap to the GND plane
  through multiple vias.
  (see the Gerber files)
- AGND
- Connect the output
  cap to the GND plane
  through multiple vias
- Connect the input
  cap to the GND plane
  through multiple vias.
  (see the Gerber files)
- AGND
- 1.2V
- Connect the output
  cap to the GND plane
  through multiple vias
- Set Vout  to 1.2V
sheet 69
- PWR - VCCE_PLL_GXR, VCCE_DTS_GXR
- PWR - VCCFUSEWR_SDM
- Vout (PG_threshold) = 0.75V
- Place close to FPGA
- PWR - VCCFUSEWR_SDM
- AGND
- Connect the input
  cap to the GND plane
  through multiple vias.
  (see the Gerber files)
- 1.8V
- Connect the output
  cap to the GND plane
  through multiple vias
- Set Vout  to 1.8V
sheet 70
- PWR - 1p2V_DDR4_CH01, VCCIO_PIO_2B/2E/2F/2C
- 1.2V @ 12A
- VIN  : 4V to 20V
- VOUT : 1V2
- RFB : {( 60.4K/4)/(VOUT/0.6)-1)}
- RFB : 15.1K
- FSW  : 1.2 MHz
- Tj   : -40 C TO 125 C
- CURRENT : 12A
- AGND
- PGND
sheet 71
- PWR - 1p2V_DDR4_CH2, VCCIO_PIO_3A/3B/3C/3D
- 1.2V @ 12A
- VIN  : 4V to 20V
- VOUT : 1V2
- RFB : {( 60.4K/4)/ ( (VOUT/0.6)-1)}
- RFB : 15.1K
- FSW  : 1.2 MHz
- Tj   : -40 C TO 125 C
- CURRENT : 12A
- AGND
- PGND
sheet 72
- PWR - DDR4 VREF/VTT
- 0.6V
- Vih=1.7, Vil = 0.3
- 0.6V
- 0.6V
- Vih=1.7, Vil = 0.3
- 0.6V
- 0.6V
- Vih=1.7, Vil = 0.3
- 0.6V
sheet 73
- PWR - 2p5V
- Connect the input
  cap to the GND plane
  through multiple vias.
  (see the Gerber files)
- 2.5V
- Connect the output
  cap to the GND plane
  through multiple vias
- AGND
- PGND
- 3.3V Enable Circuit
